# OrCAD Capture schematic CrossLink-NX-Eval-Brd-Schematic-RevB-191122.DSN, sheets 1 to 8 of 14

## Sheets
1 Title Page: title: Title page; rev: 1.0; note: 305-PD-19-0819
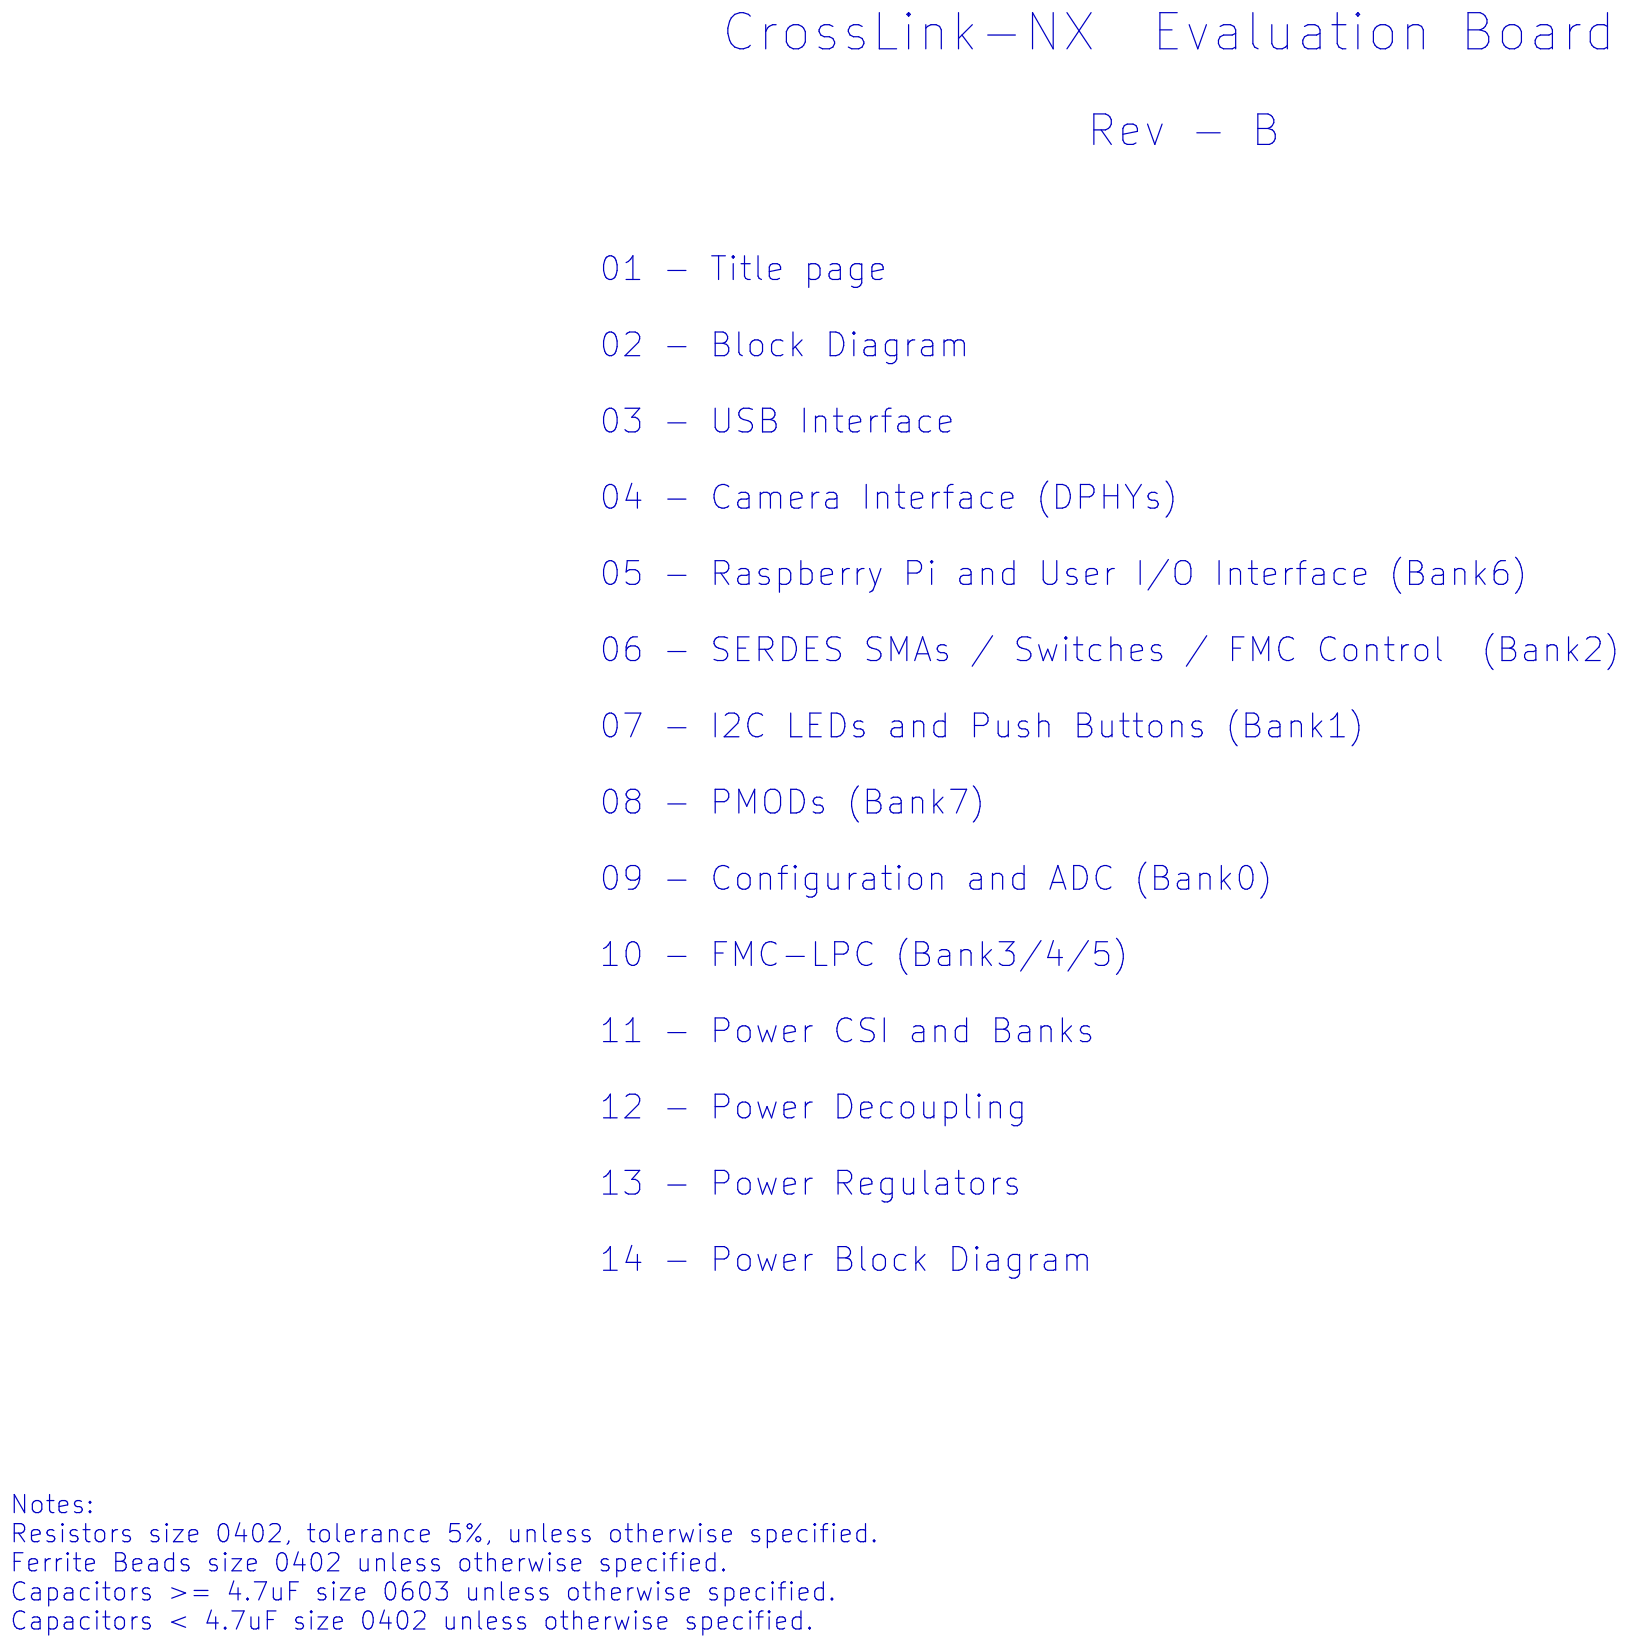
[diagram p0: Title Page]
2 Block Diagram: title: Block Diagram
3 USB Interface: size B; title: USB Interface
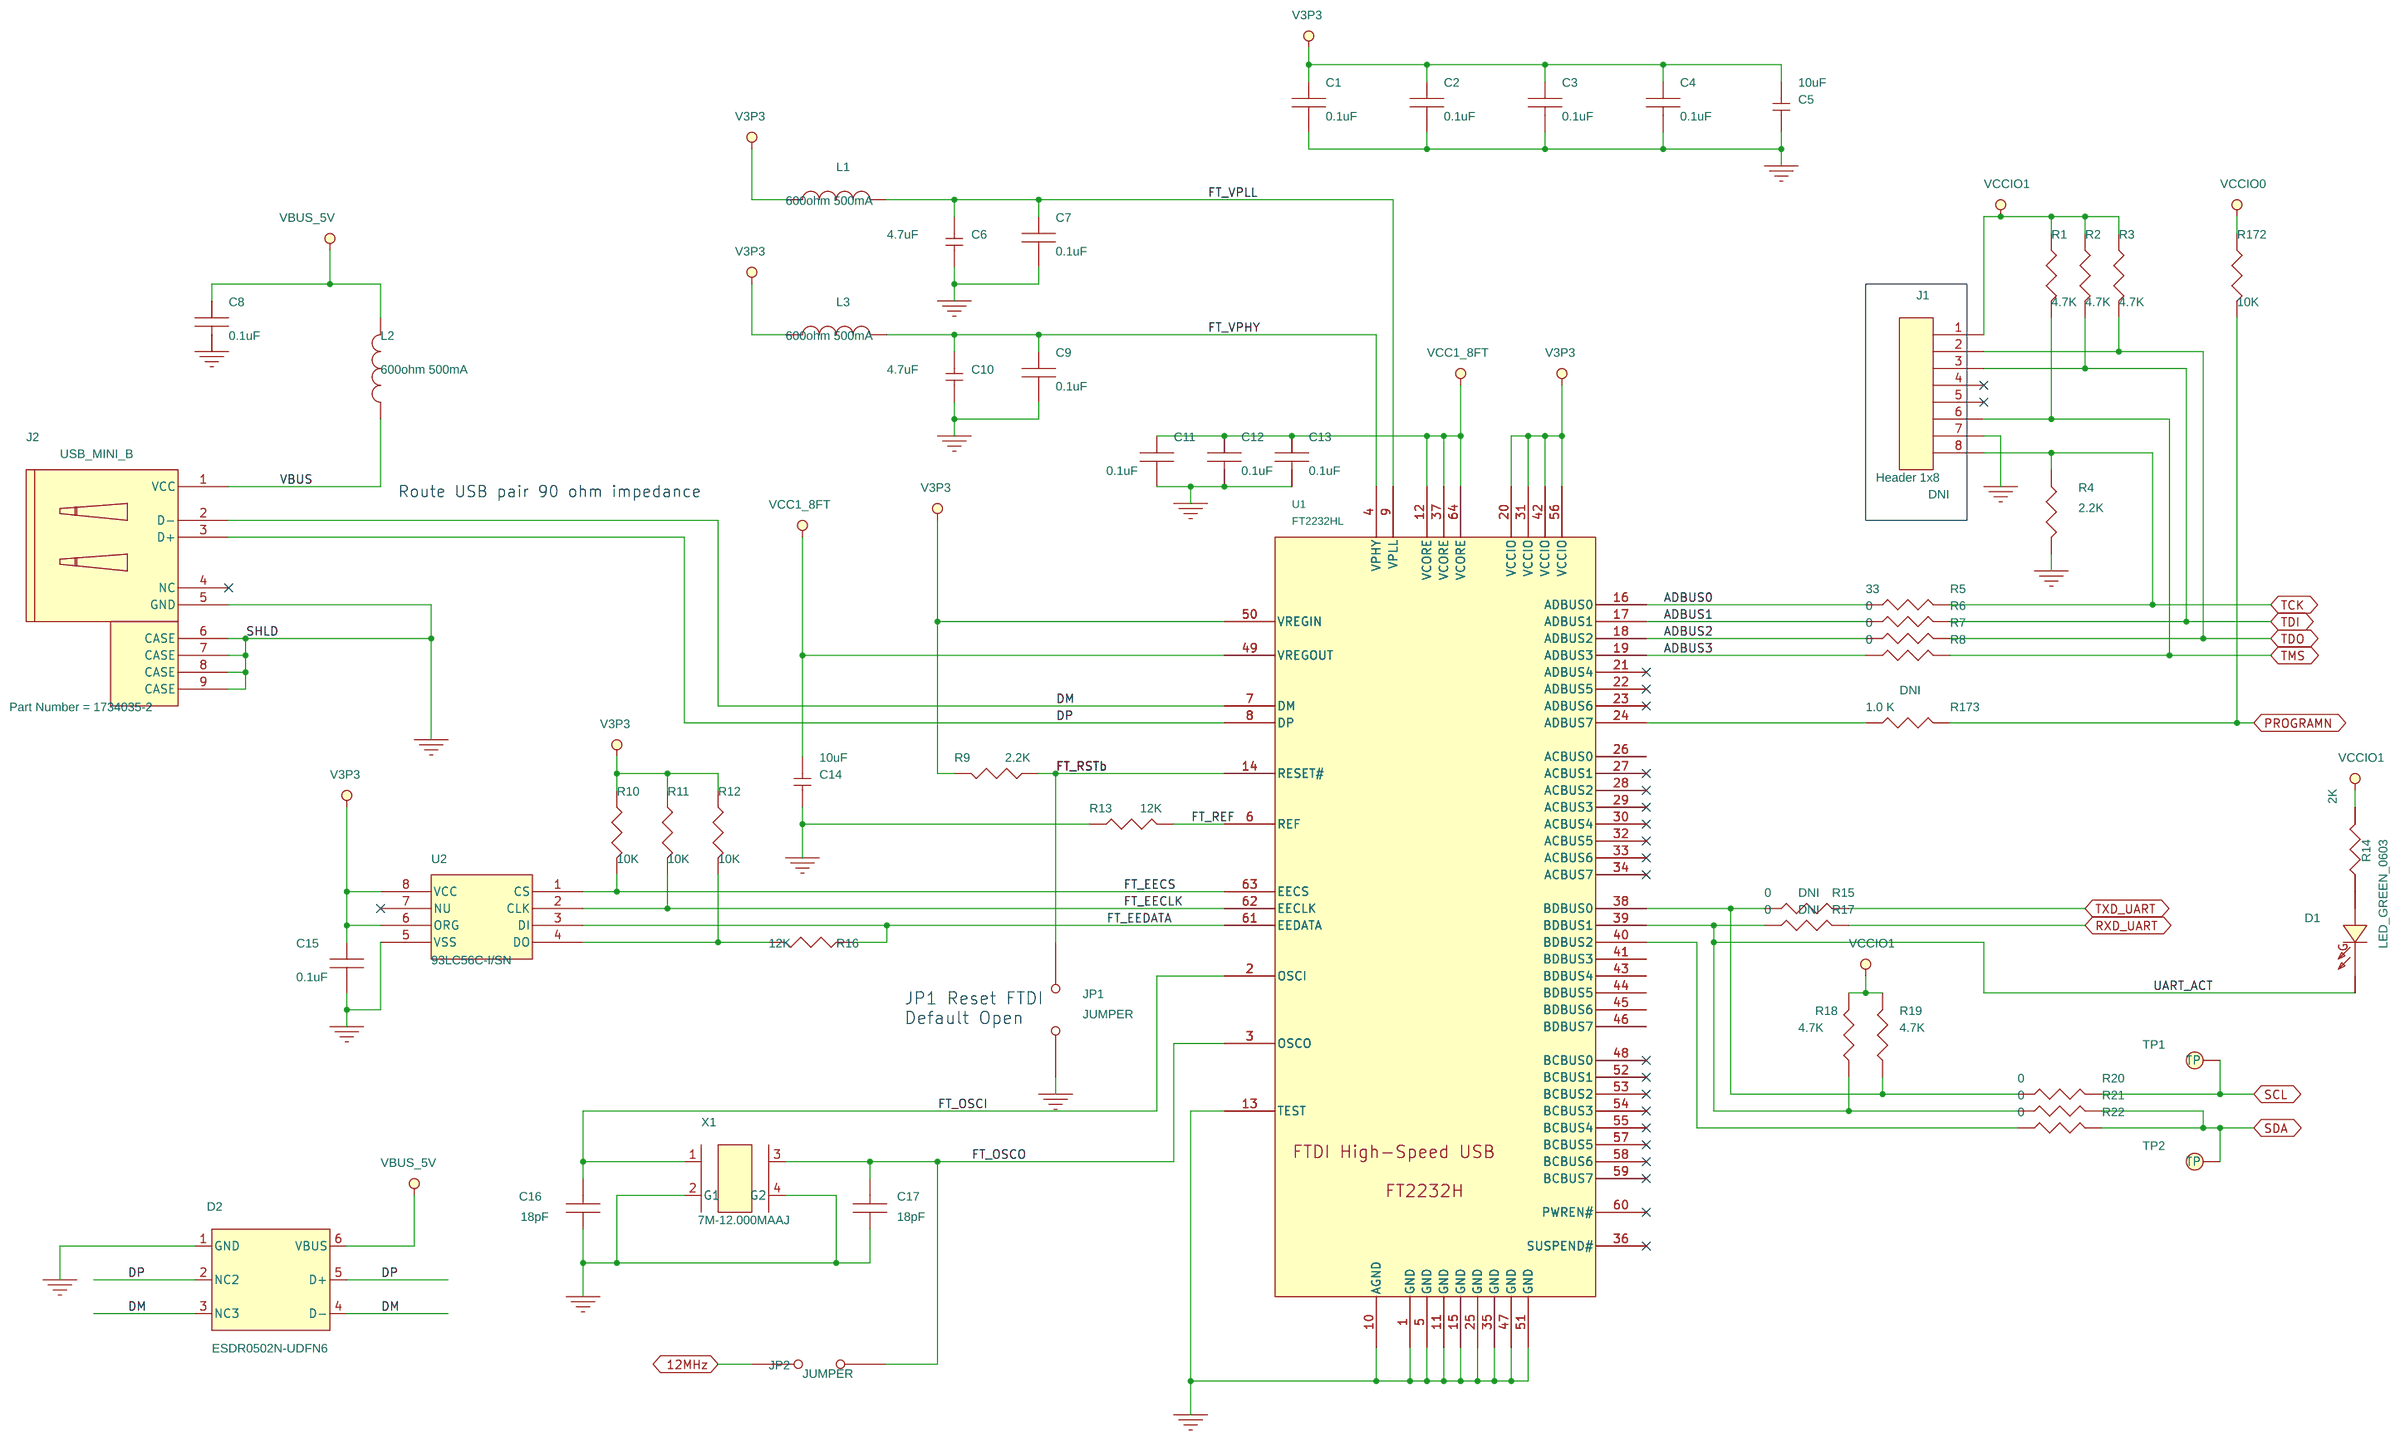
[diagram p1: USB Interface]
4 Camera Interface: size B; title: Camera Interface (DPHYs)
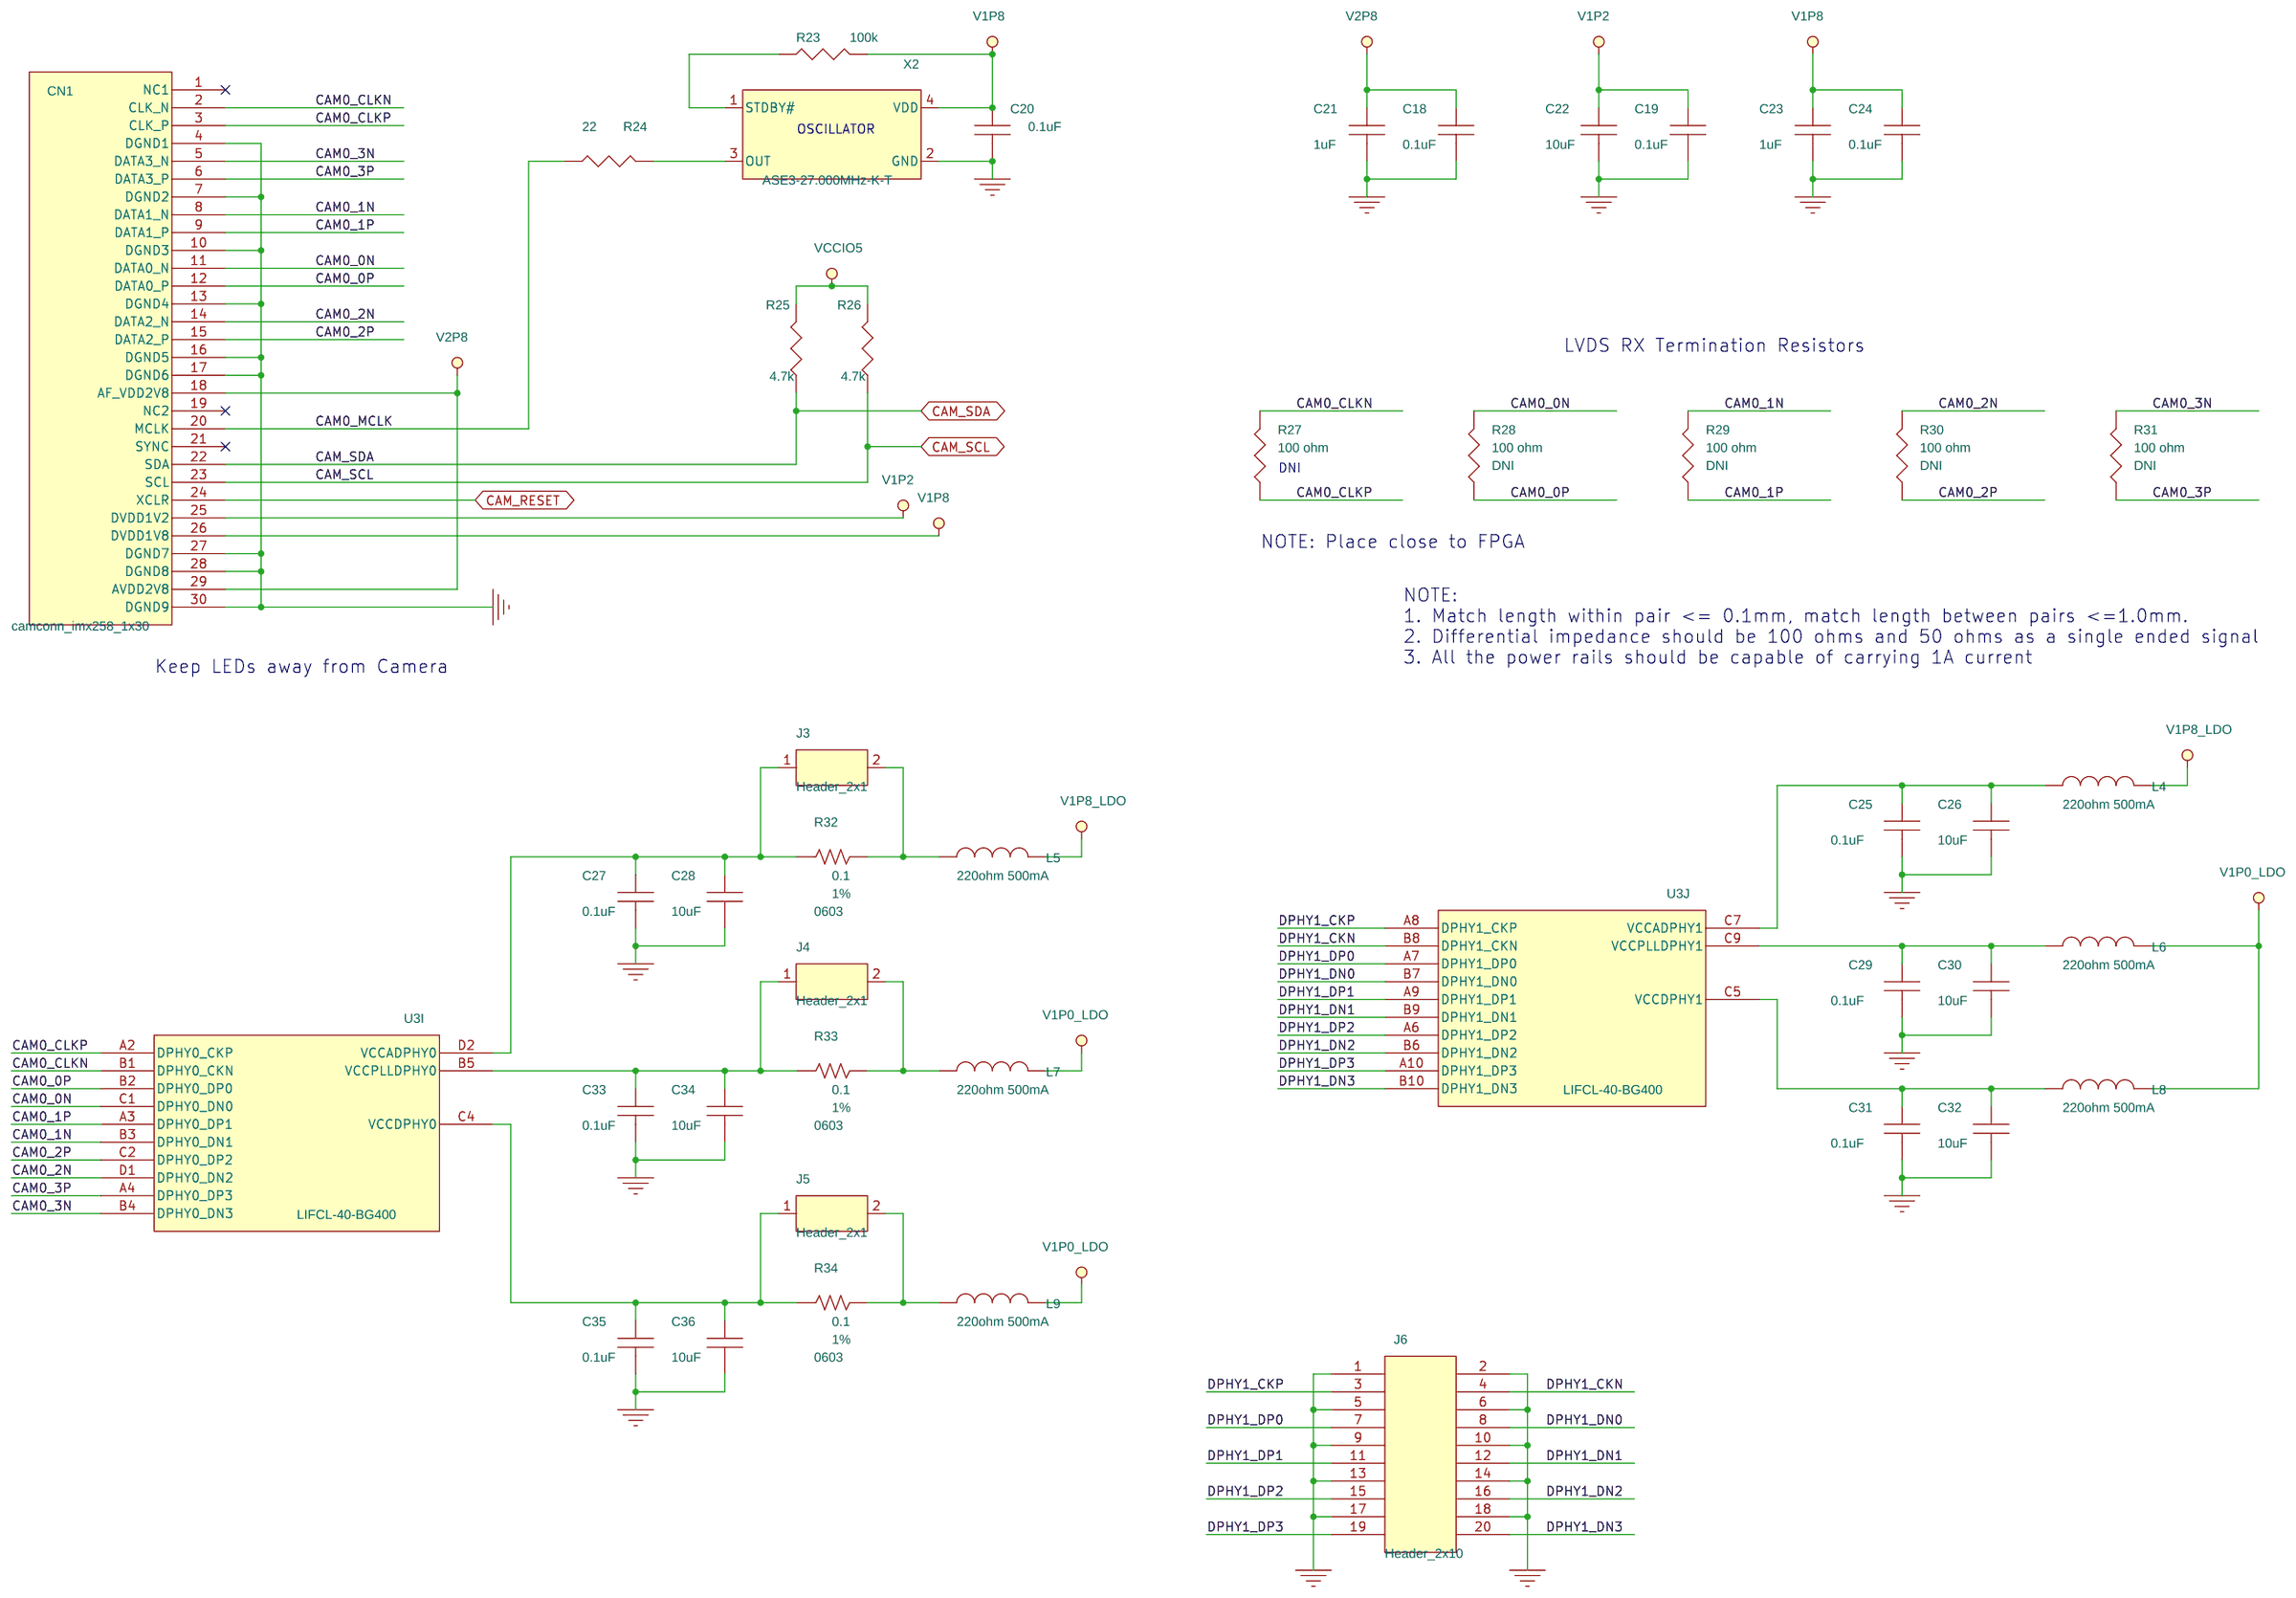
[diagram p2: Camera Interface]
5 Raspberry Pi: size B; title: Raspberry Pi and User I/O Interface
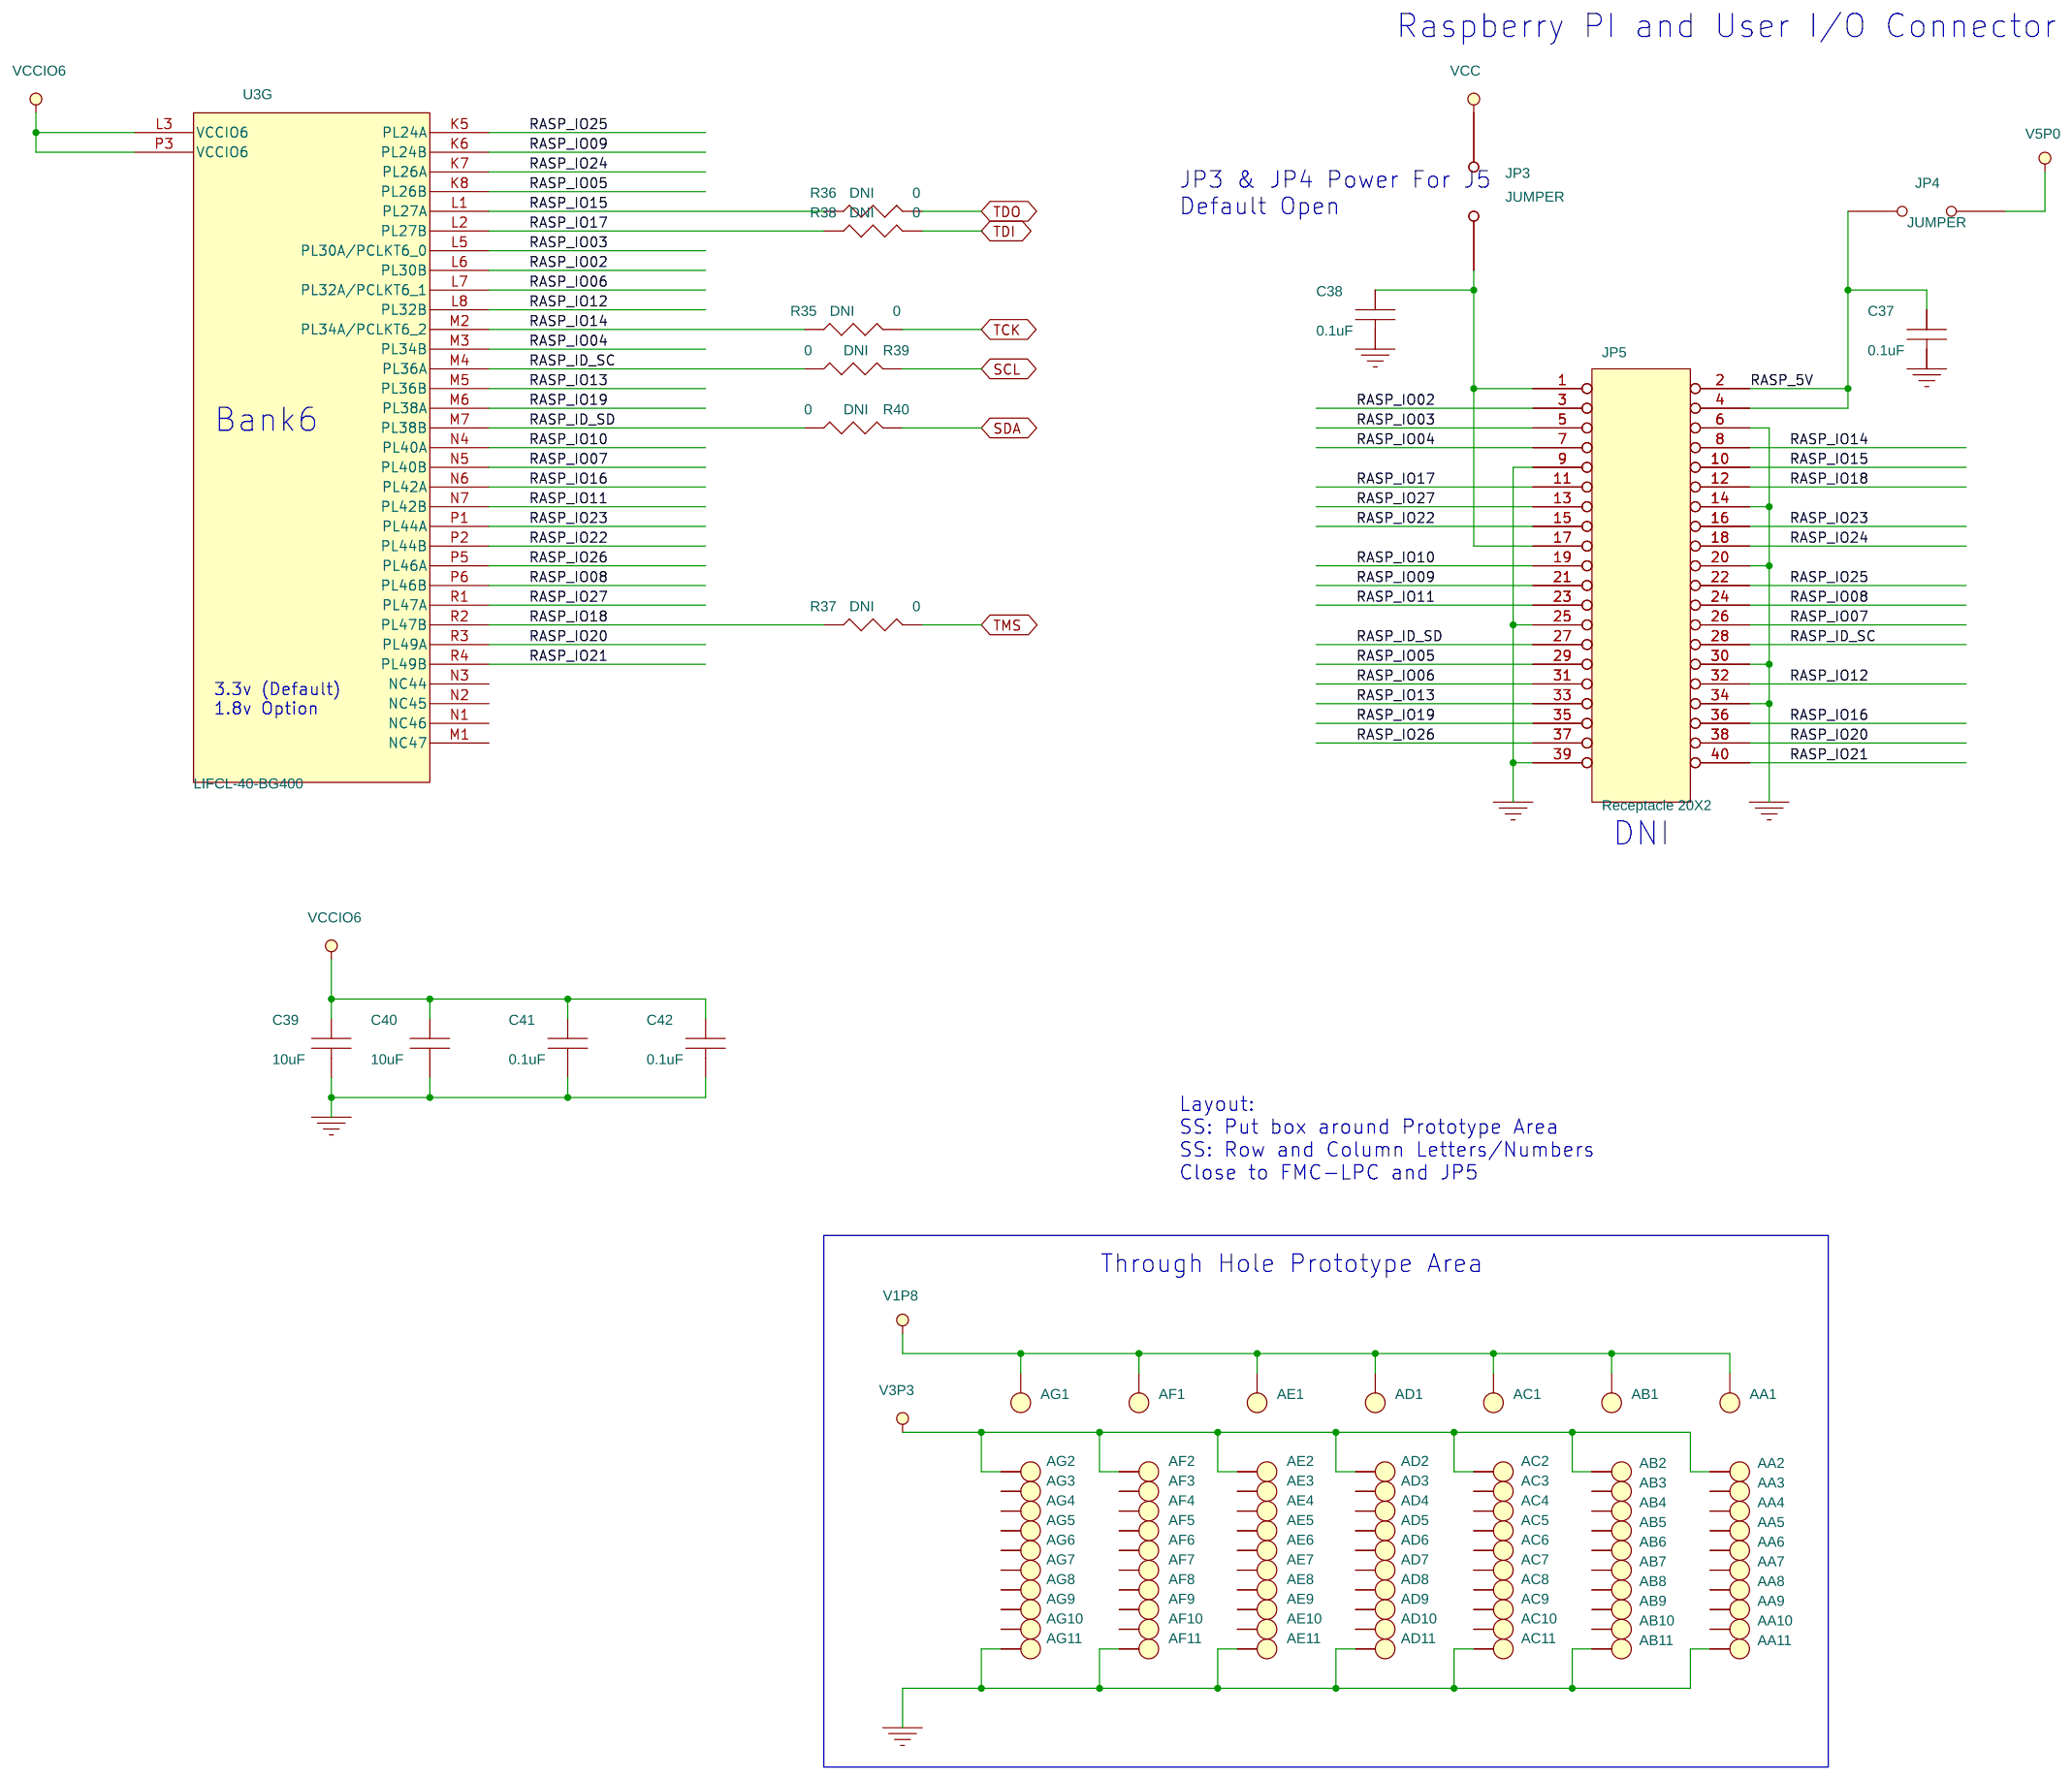
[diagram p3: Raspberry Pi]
6 Serdes SMAs And Switches: size B; title: Serdes SMAs/Switches/FMC Control
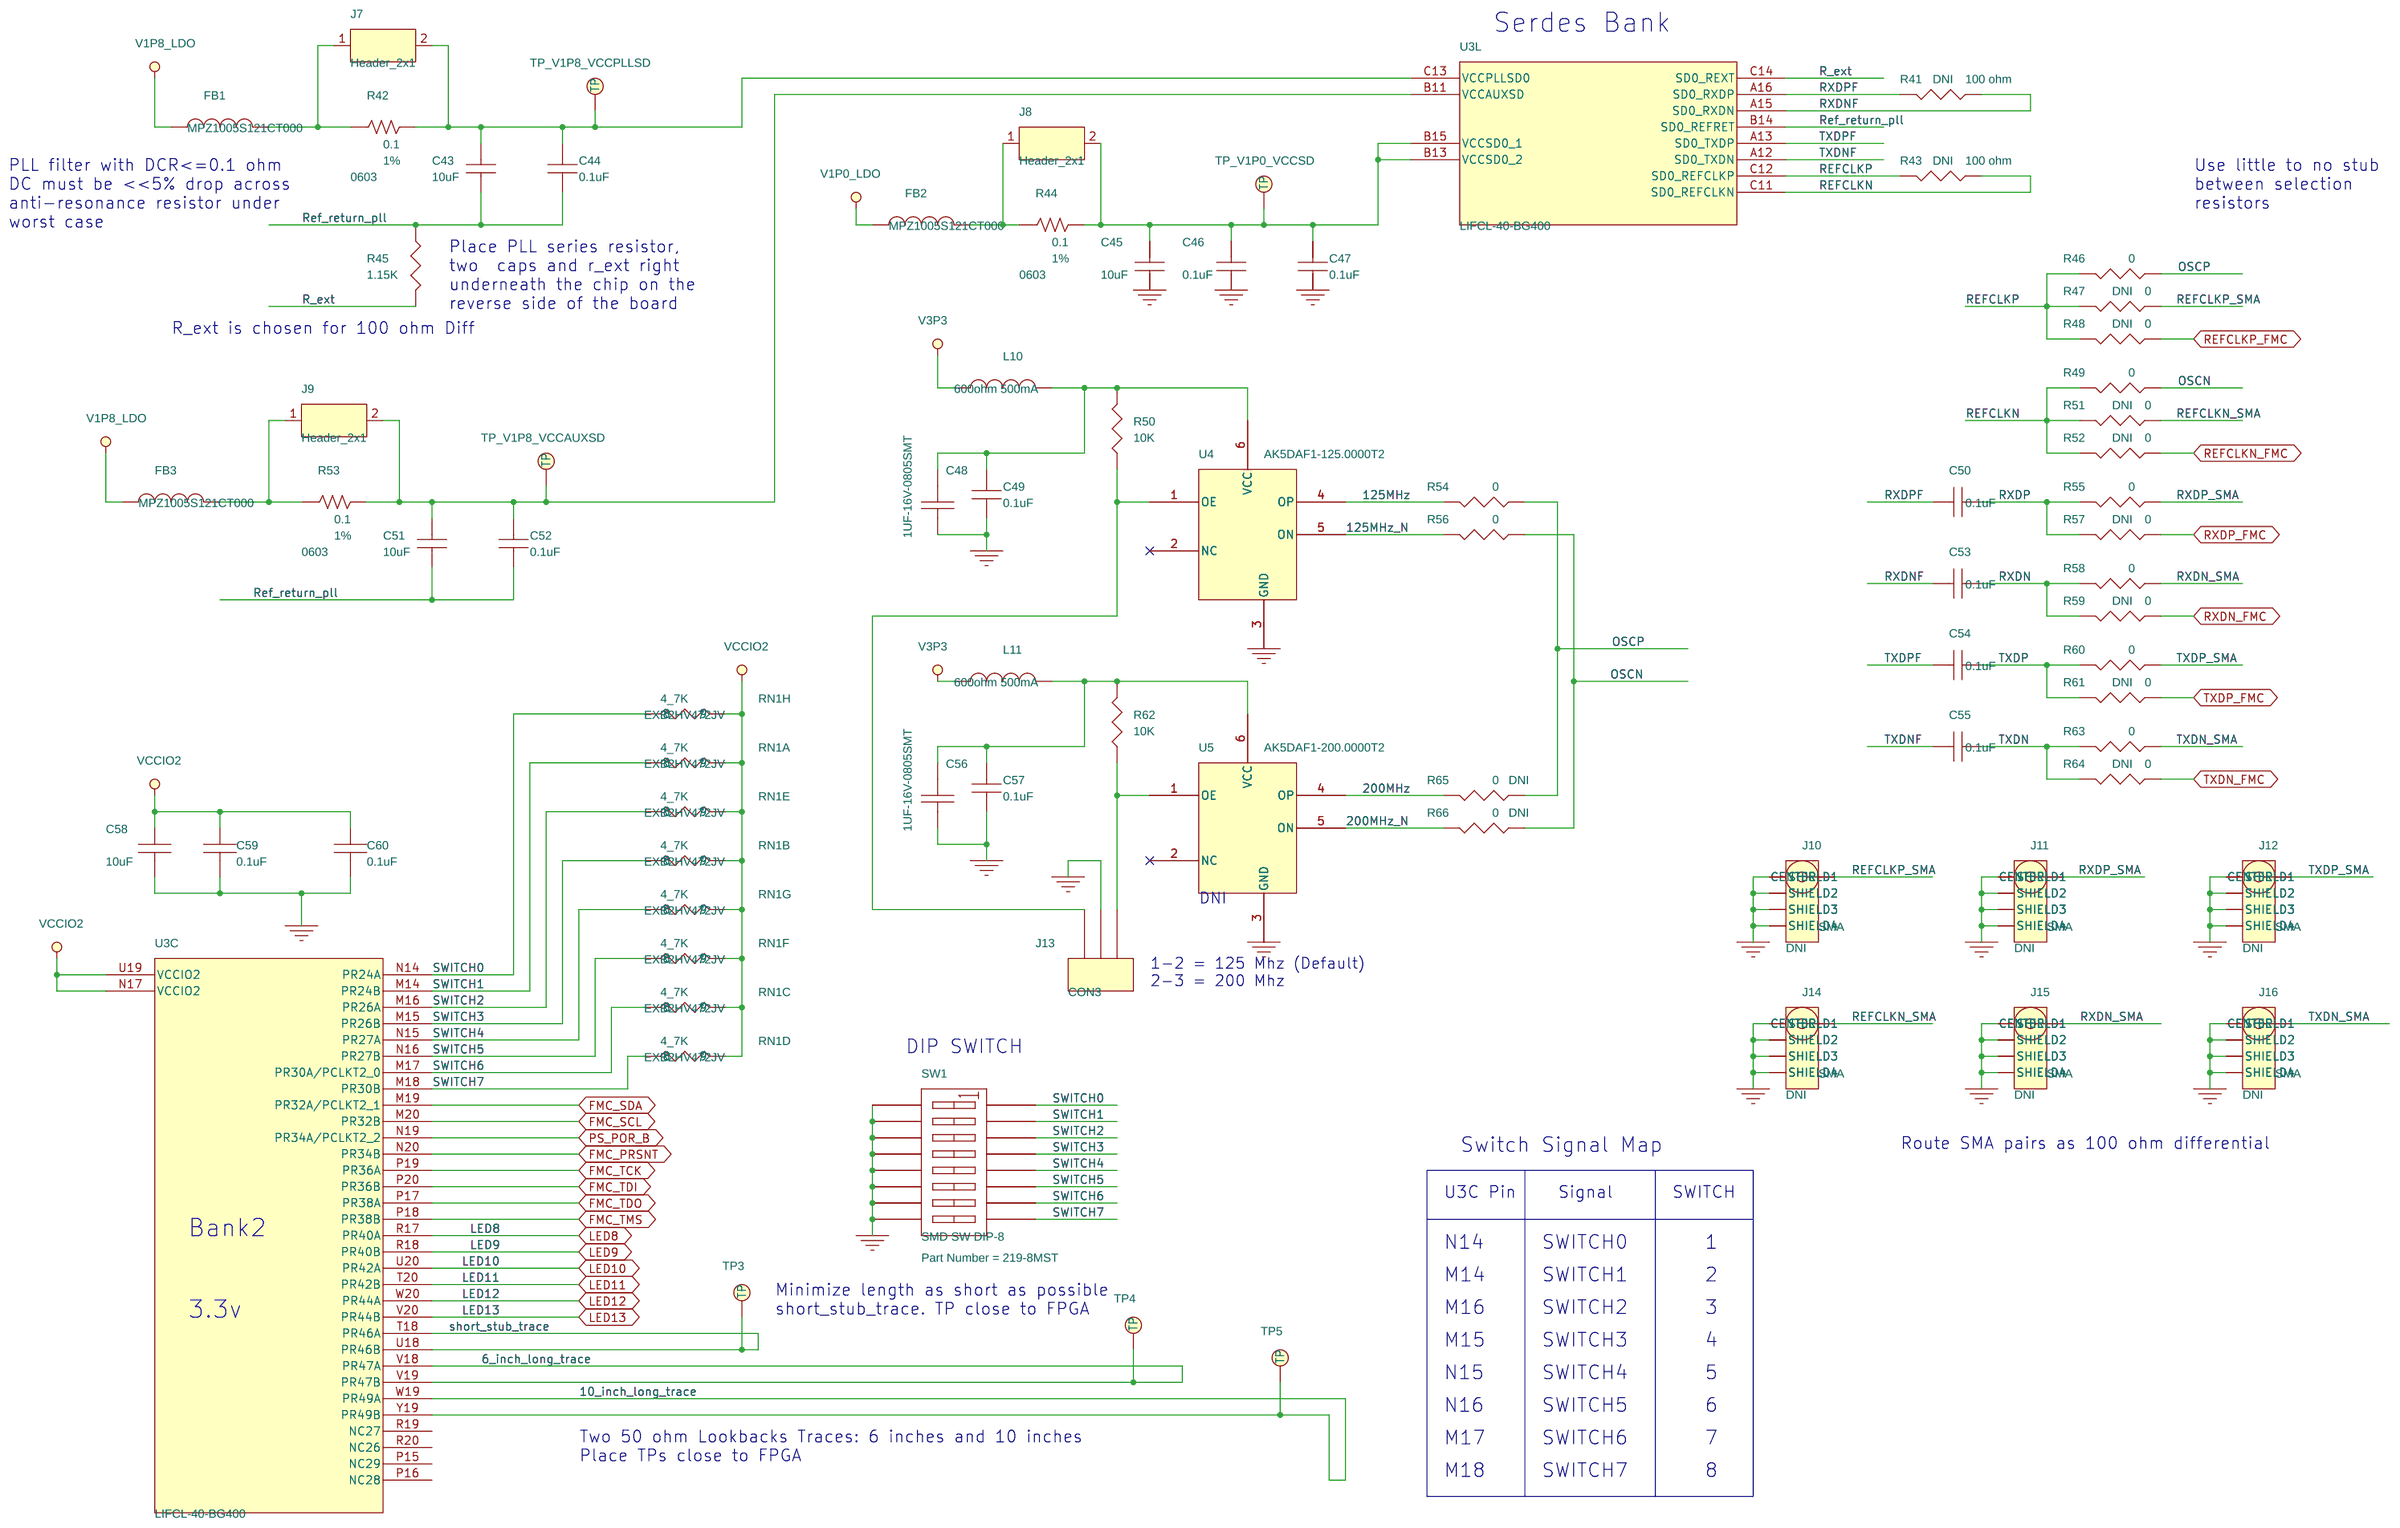
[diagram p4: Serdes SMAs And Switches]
7 I2C, LEDs And Push Button: size B; title: I2C LEDs And Push Buttons
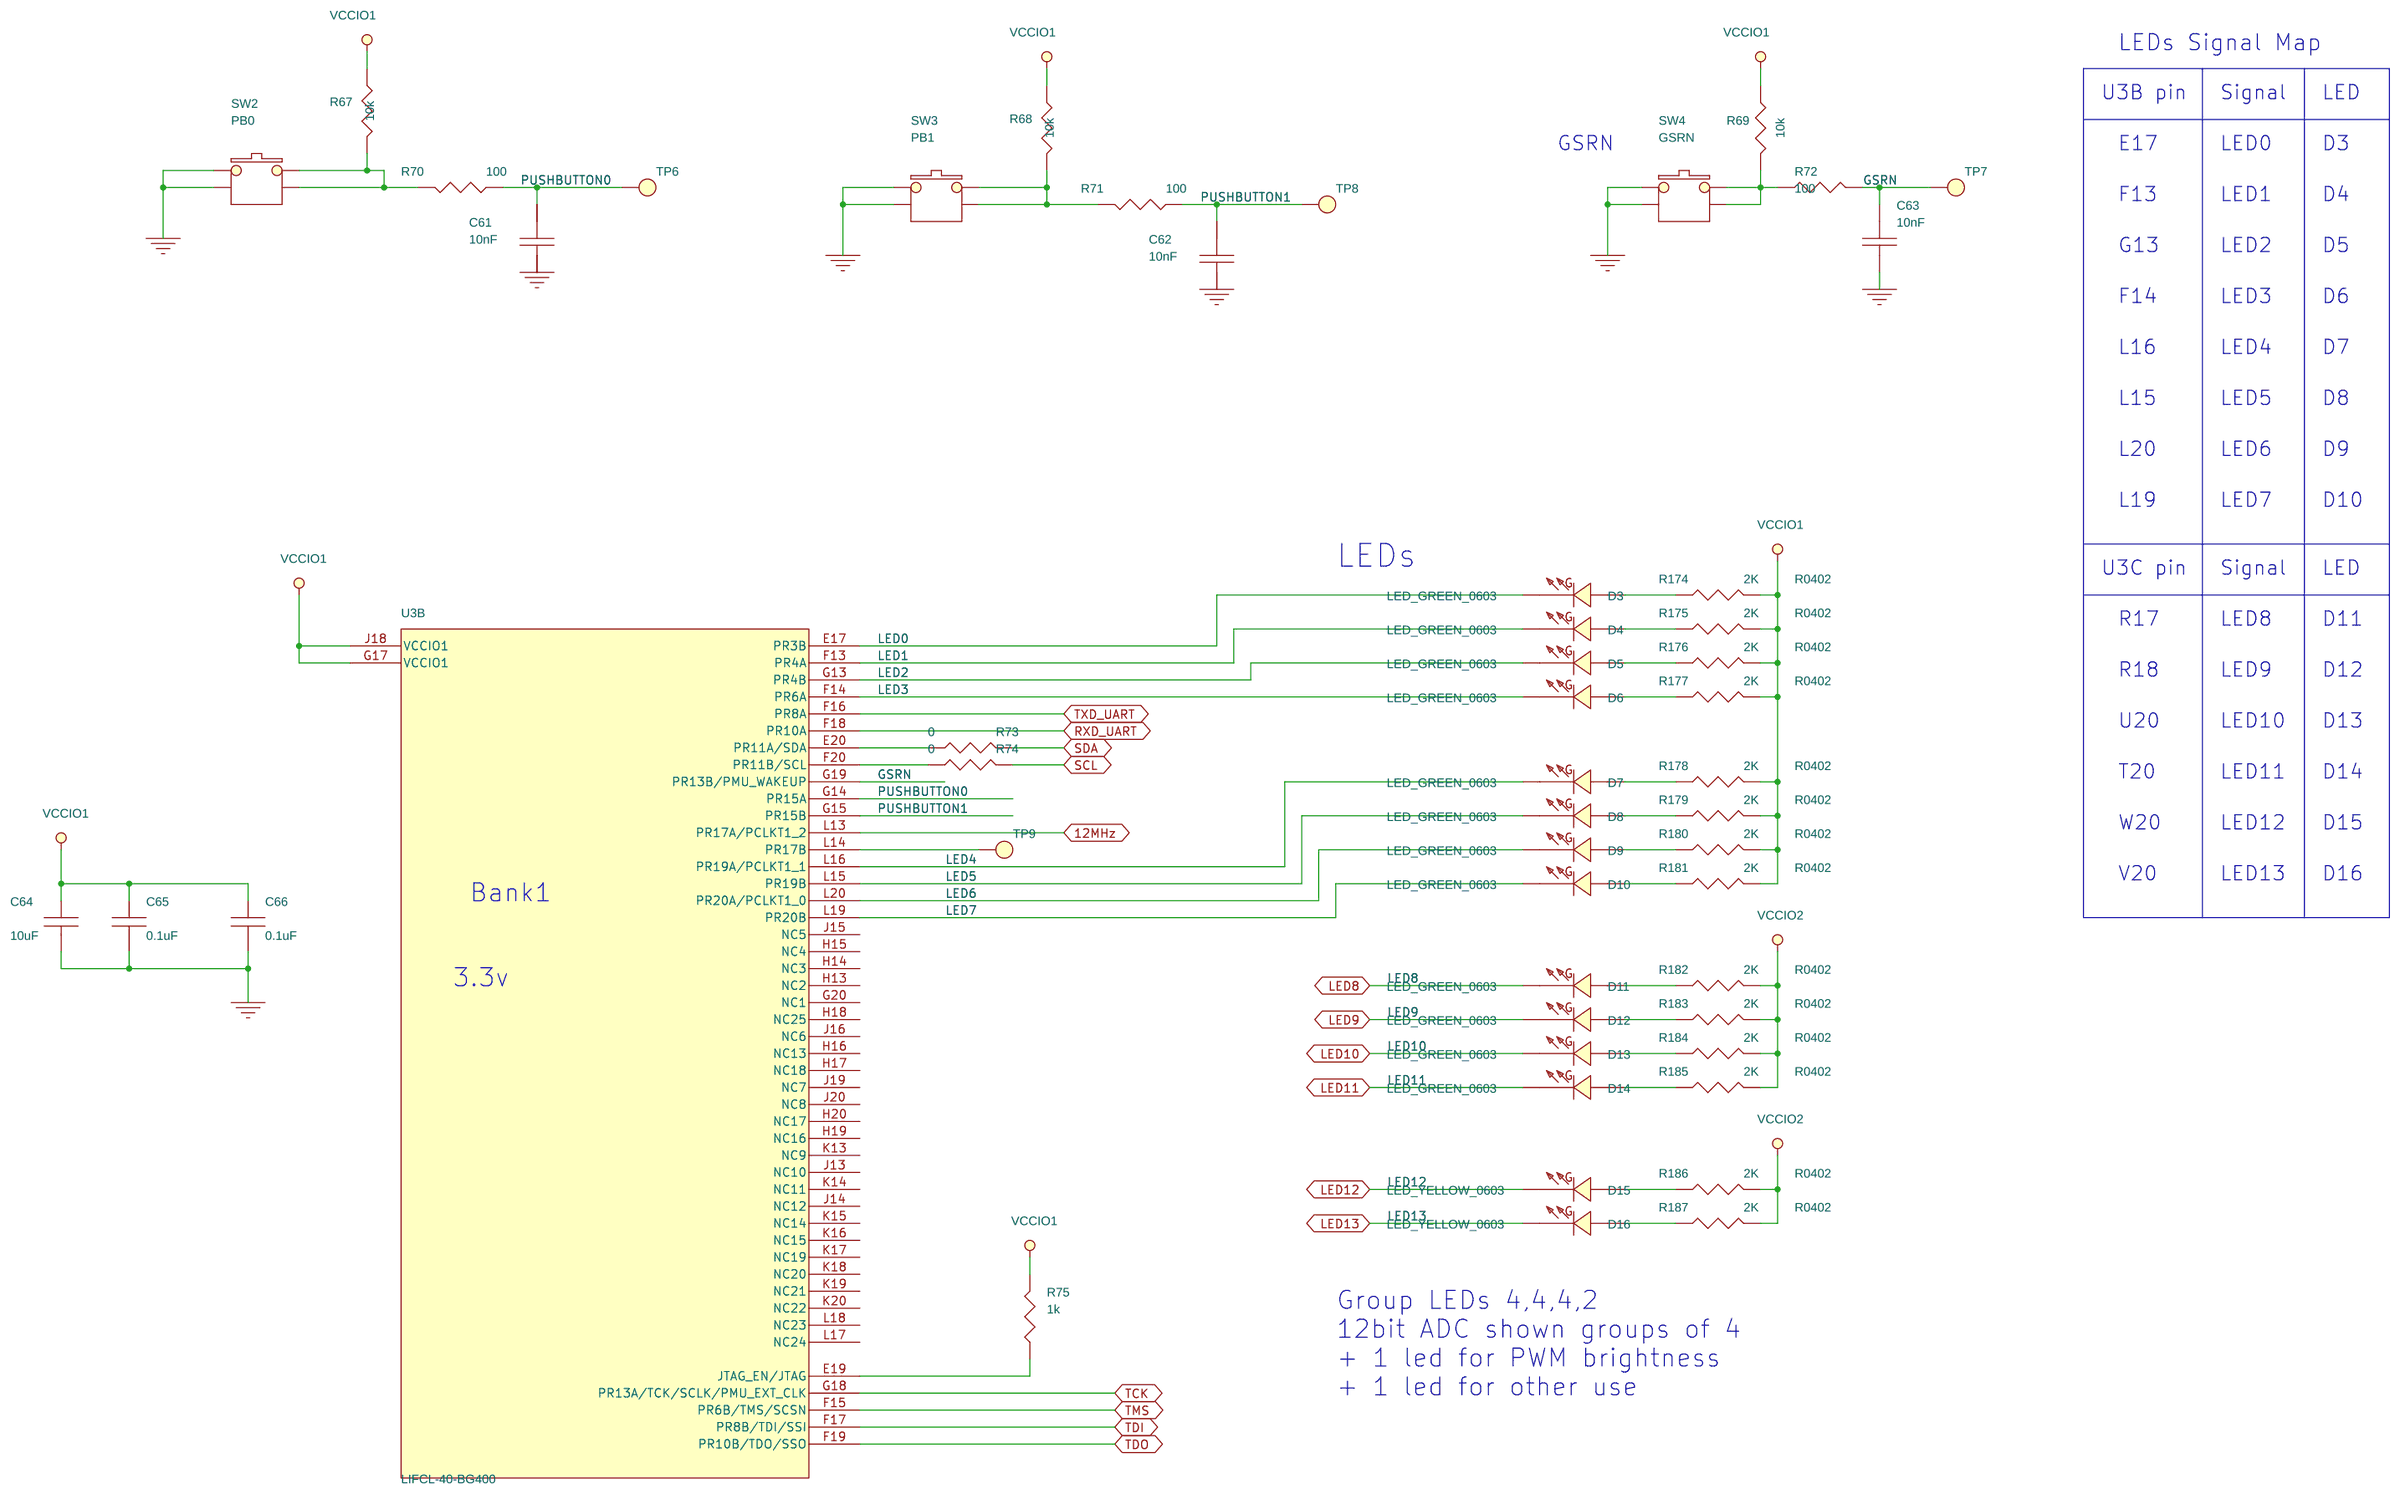
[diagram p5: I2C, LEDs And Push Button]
8 PMOD: size B; title: PMODs
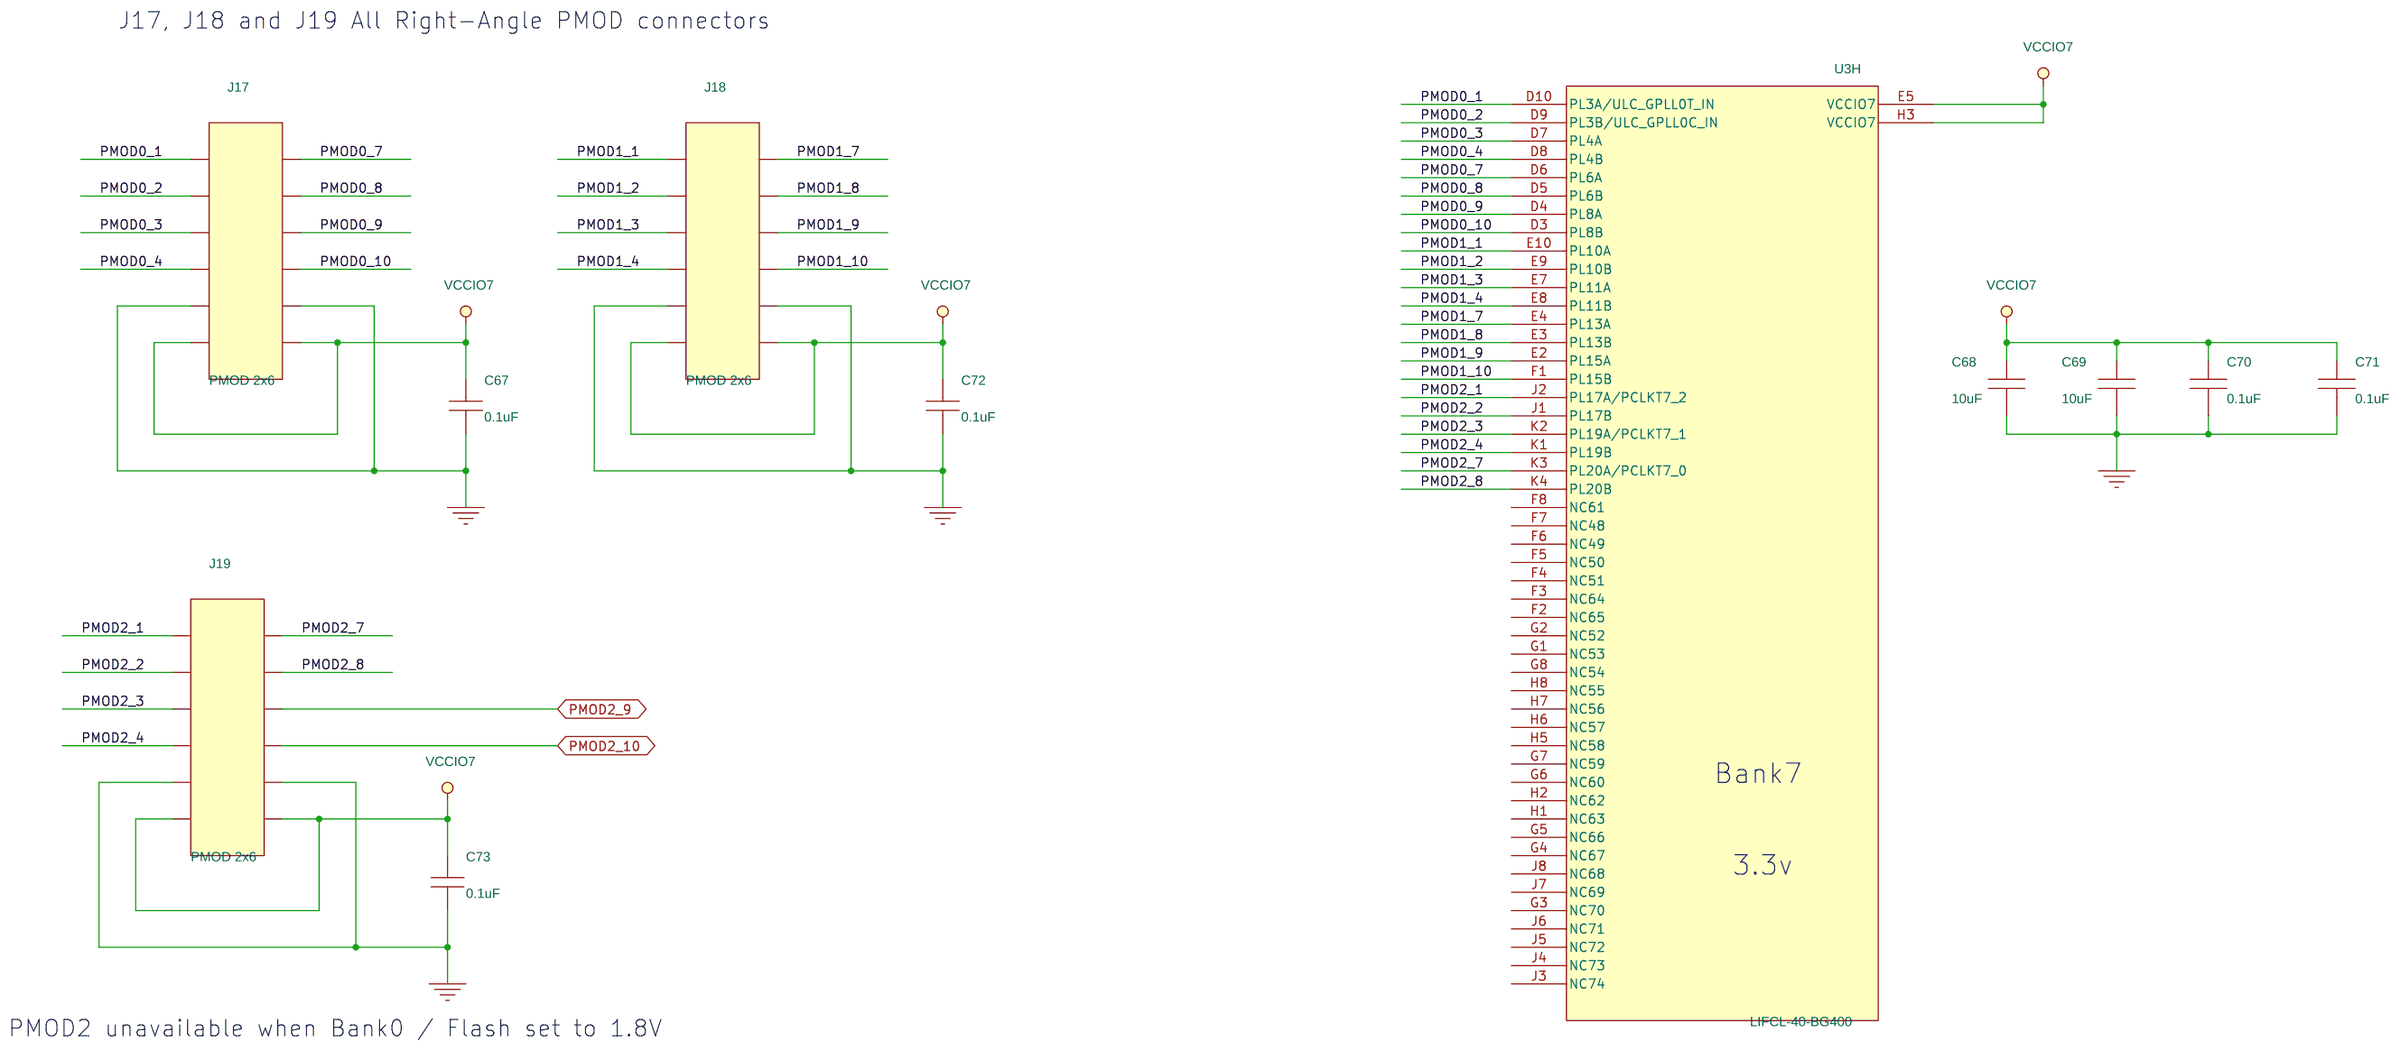
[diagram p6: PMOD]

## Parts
sheet Camera Interface
C18  0.1uF  [C0201]
C19  0.1uF  [C0201]
C20  0.1uF  [C0201]
C21  1uF  [C0603]
C22  10uF  [C0603]
C23  1uF  [C0603]
C24  0.1uF  [C0201]
C25  0.1uF  [C0201]
C26  10uF  [C0402]
C27  0.1uF  [C0201]
C28  10uF  [C0402]
C29  0.1uF  [C0201]
C30  10uF  [C0402]
C31  0.1uF  [C0201]
C32  10uF  [C0402]
C33  0.1uF  [C0201]
C34  10uF  [C0402]
C35  0.1uF  [C0201]
C36  10uF  [C0402]
CN1  camconn_imx258_1x30  [camconn]
J3  Header_2x1  [Header_2x1]
J4  Header_2x1  [Header_2x1]
J5  Header_2x1  [Header_2x1]
J6  Header_2x10  [Header_2x10]
L4  220ohm 500mA  [FB0402]
L5  220ohm 500mA  [FB0402]
L6  220ohm 500mA  [FB0402]
L7  220ohm 500mA  [FB0402]
L8  220ohm 500mA  [FB0402]
L9  220ohm 500mA  [FB0402]
R23  100k  [R0402]
R24  22  [R0402]
R25  4.7k  [R0402]
R26  4.7k  [R0402]
R27  100 ohm  [R0201]
R28  100 ohm  [R0201]
R29  100 ohm  [R0201]
R30  100 ohm  [R0201]
R31  100 ohm  [R0201]
R32  0.1  [0603]
R33  0.1  [0603]
R34  0.1  [0603]
X2  ASE3-27.000MHz-K-T  [27MHZ]
sheet I2C, LEDs And Push Button
C61  10nF  [RLP-130-A]
C62  10nF  [RLP-130-A]
C63  10nF  [RLP-130-A]
C64  10uF  [C0603]
C65  0.1uF  [C0201]
C66  0.1uF  [C0201]
D3  LED_GREEN_0603  [APT1608]
D4  LED_GREEN_0603  [APT1608]
D5  LED_GREEN_0603  [APT1608]
D6  LED_GREEN_0603  [APT1608]
D7  LED_GREEN_0603  [APT1608]
D8  LED_GREEN_0603  [APT1608]
D9  LED_GREEN_0603  [APT1608]
D10  LED_GREEN_0603  [APT1608]
D11  LED_GREEN_0603  [APT1608]
D12  LED_GREEN_0603  [APT1608]
D13  LED_GREEN_0603  [APT1608]
D14  LED_GREEN_0603  [APT1608]
D15  LED_YELLOW_0603  [APT1608]
D16  LED_YELLOW_0603  [APT1608]
R67  10k  [R0402]
R68  10k  [R0402]
R69  10k  [R0402]
R70  100  [R0402]
R71  100  [R0402]
R72  100  [R0402]
R73  0  [R0402]
R74  0  [R0402]
R75  1k  [R0402]
R174  2K  [R0402]
R175  2K  [R0402]
R176  2K  [R0402]
R177  2K  [R0402]
R178  2K  [R0402]
R179  2K  [R0402]
R180  2K  [R0402]
R181  2K  [R0402]
R182  2K  [R0402]
R183  2K  [R0402]
R184  2K  [R0402]
R185  2K  [R0402]
R186  2K  [R0402]
R187  2K  [R0402]
SW2  PB0  [4psmd_switch]
SW3  PB1  [4psmd_switch]
SW4  GSRN  [4psmd_switch]
TP6  TestPoint  [TP50]
TP7  TestPoint  [TP50]
TP8  TestPoint  [TP50]
TP9  TestPoint  [TP50]
sheet PMOD
C67  0.1uF  [C0201]
C68  10uF  [C0603]
C69  10uF  [C0603]
C70  0.1uF  [C0201]
C71  0.1uF  [C0201]
C72  0.1uF  [C0201]
C73  0.1uF  [C0201]
J17  PMOD 2x6  [PPPC062LJBN-RC]
J18  PMOD 2x6  [PPPC062LJBN-RC]
J19  PMOD 2x6  [PPPC062LJBN-RC]
sheet Raspberry Pi
AA1  T POINT R  [TP]
AA2  T POINT R  [TP]
AA3  T POINT R  [TP]
AA4  T POINT R  [TP]
AA5  T POINT R  [TP]
AA6  T POINT R  [TP]
AA7  T POINT R  [TP]
AA8  T POINT R  [TP]
AA9  T POINT R  [TP]
AA10  T POINT R  [TP]
AA11  T POINT R  [TP]
AB1  T POINT R  [TP]
AB2  T POINT R  [TP]
AB3  T POINT R  [TP]
AB4  T POINT R  [TP]
AB5  T POINT R  [TP]
AB6  T POINT R  [TP]
AB7  T POINT R  [TP]
AB8  T POINT R  [TP]
AB9  T POINT R  [TP]
AB10  T POINT R  [TP]
AB11  T POINT R  [TP]
AC1  T POINT R  [TP]
AC2  T POINT R  [TP]
AC3  T POINT R  [TP]
AC4  T POINT R  [TP]
AC5  T POINT R  [TP]
AC6  T POINT R  [TP]
AC7  T POINT R  [TP]
AC8  T POINT R  [TP]
AC9  T POINT R  [TP]
AC10  T POINT R  [TP]
AC11  T POINT R  [TP]
AD1  T POINT R  [TP]
AD2  T POINT R  [TP]
AD3  T POINT R  [TP]
AD4  T POINT R  [TP]
AD5  T POINT R  [TP]
AD6  T POINT R  [TP]
AD7  T POINT R  [TP]
AD8  T POINT R  [TP]
AD9  T POINT R  [TP]
AD10  T POINT R  [TP]
AD11  T POINT R  [TP]
AE1  T POINT R  [TP]
AE2  T POINT R  [TP]
AE3  T POINT R  [TP]
AE4  T POINT R  [TP]
AE5  T POINT R  [TP]
AE6  T POINT R  [TP]
AE7  T POINT R  [TP]
AE8  T POINT R  [TP]
AE9  T POINT R  [TP]
AE10  T POINT R  [TP]
AE11  T POINT R  [TP]
AF1  T POINT R  [TP]
AF2  T POINT R  [TP]
AF3  T POINT R  [TP]
AF4  T POINT R  [TP]
AF5  T POINT R  [TP]
AF6  T POINT R  [TP]
AF7  T POINT R  [TP]
AF8  T POINT R  [TP]
AF9  T POINT R  [TP]
AF10  T POINT R  [TP]
AF11  T POINT R  [TP]
AG1  T POINT R  [TP]
AG2  T POINT R  [TP]
AG3  T POINT R  [TP]
AG4  T POINT R  [TP]
AG5  T POINT R  [TP]
AG6  T POINT R  [TP]
AG7  T POINT R  [TP]
AG8  T POINT R  [TP]
AG9  T POINT R  [TP]
AG10  T POINT R  [TP]
AG11  T POINT R  [TP]
C37  0.1uF  [C0201]
C38  0.1uF  [C0201]
C39  10uF  [C0603]
C40  10uF  [C0603]
C41  0.1uF  [C0201]
C42  0.1uF  [C0201]
JP3  JUMPER  [Header_1x2]
JP4  JUMPER  [Header_1x2]
JP5  Receptacle 20X2  [HDR254-2X20_socket]
R35  0  [R0603]
R36  0  [R0603]
R37  0  [R0603]
R38  0  [R0603]
R39  0  [R0603]
R40  0  [R0603]
U3  LIFCL-40-BG400  [LIFCL-40-BG400]  (sections A,B,C,D,E,F,G,H,I,J,K,L,M,N,O)
sheet Serdes SMAs And Switches
C43  10uF  [C0402]
C44  0.1uF  [C0201]
C45  10uF  [C0402]
C46  0.1uF  [C0201]
C47  0.1uF  [C0201]
C48  1UF-16V-0805SMT  [RLP-133]
C49  0.1uF  [C0201]
C50  0.1uF  [C0201]
C51  10uF  [C0402]
C52  0.1uF  [C0201]
C53  0.1uF  [C0201]
C54  0.1uF  [C0201]
C55  0.1uF  [C0201]
C56  1UF-16V-0805SMT  [RLP-133]
C57  0.1uF  [C0201]
C58  10uF  [C0603]
C59  0.1uF  [C0201]
C60  0.1uF  [C0201]
FB1  MPZ1005S121CT000  [FB0402]
FB2  MPZ1005S121CT000  [FB0402]
FB3  MPZ1005S121CT000  [FB0402]
J7  Header_2x1  [Header_2x1]
J8  Header_2x1  [Header_2x1]
J9  Header_2x1  [Header_2x1]
J10  SMA  [901-10309]
J11  SMA  [901-10309]
J12  SMA  [901-10309]
J13  CON3  [CON3]
J14  SMA  [901-10309]
J15  SMA  [901-10309]
J16  SMA  [901-10309]
L10  600ohm 500mA  [fb0603]
L11  600ohm 500mA  [fb0603]
R41  100 ohm  [R0201]
R42  0.1  [0603]
R43  100 ohm  [R0201]
R44  0.1  [0603]
R45  1.15K  [R0402]
R46  0  [R0402]
R47  0  [R0402]
R48  0  [R0402]
R49  0  [R0402]
R50  10K  [RLP-100]
R51  0  [R0402]
R52  0  [R0402]
R53  0.1  [0603]
R54  0  [R0402]
R55  0  [R0402]
R56  0  [R0402]
R57  0  [R0402]
R58  0  [R0402]
R59  0  [R0402]
R60  0  [R0402]
R61  0  [R0402]
R62  10K  [RLP-100]
R63  0  [R0402]
R64  0  [R0402]
R65  0  [R0402]
R66  0  [R0402]
RN1  EXB2HV472JV  [EXB-2HV]  (sections A,B,C,D,E,F,G,H)
SW1  SMD SW DIP-8  [219-8MST]
TP3  TP_S_40_63  [TP]
TP4  TP_S_40_63  [TP]
TP5  TP_S_40_63  [TP]
TP_V1P0_VCCSD  TP_S_40_63  [tp_s_40_63]
TP_V1P8_VCCAUXSD  TP_S_40_63  [tp_s_40_63]
TP_V1P8_VCCPLLSD  TP_S_40_63  [tp_s_40_63]
U4  AK5DAF1-125.0000T2  [XTAL_AK5DAF1]
U5  AK5DAF1-200.0000T2  [XTAL_AK5DAF1]
sheet USB Interface
C1  0.1uF  [C0201]
C2  0.1uF  [C0201]
C3  0.1uF  [C0201]
C4  0.1uF  [C0201]
C5  10uF  [C0603]
C6  4.7uF  [C0603]
C7  0.1uF  [C0201]
C8  0.1uF  [C0201]
C9  0.1uF  [C0201]
C10  4.7uF  [C0603]
C11  0.1uF  [C0201]
C12  0.1uF  [C0201]
C13  0.1uF  [C0201]
C14  10uF  [C0603]
C15  0.1uF  [C0201]
C16  18pF  [C0402]
C17  18pF  [C0402]
D1  LED_GREEN_0603  [APT1608]
D2  ESDR0502N-UDFN6  [UDFN6_040]
J1  Header 1x8  [hdr_amp_87220_8_1x8_100]
J2  USB_MINI_B  [USB_MINI_B-1734035-2]
JP1  JUMPER  [Header_1x2]
JP2  JUMPER  [Header_1x2]
L1  600ohm 500mA  [fb0603]
L2  600ohm 500mA  [fb0603]
L3  600ohm 500mA  [fb0603]
R1  4.7K  [R0603]
R2  4.7K  [R0603]
R3  4.7K  [R0603]
R4  2.2K  [R0603]
R5  33  [R0402]
R6  0  [R0603]
R7  0  [R0603]
R8  0  [R0603]
R9  2.2K  [R0603]
R10  10K  [R0603]
R11  10K  [R0603]
R12  10K  [R0603]
R13  12K  [R0603]
R14  2K  [RLP-101]
R15  0  [R0603]
R16  12K  [R0603]
R17  0  [R0603]
R18  4.7K  [RLP-101]
R19  4.7K  [RLP-101]
R20  0  [R0603]
R21  0  [R0603]
R22  0  [R0603]
R172  10K  [R0603]
R173  1.0 K  [R0603]
TP1  TP_S_40_63  [TP]
TP2  TP_S_40_63  [TP]
U1  FT2232HL  [tqfp64_0p5_12p2x12p2_h1p6]
U2  93LC56C-I/SN  [so8_50_244]
X1  7M-12.000MAAJ  [xtal_4p_7m]

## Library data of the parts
C1-C4 C7-C9 C11-C13 C15 C18-C20 C24 C25 C27 C29 C31 C33 C35 C37 C38 C41 C42 C59 C60 C65 C66 C70 C71 = 0u1_0402: CAP CER 0.1UF 25V 10% X5R 0201; Manufacturer: Murata; Manufacturer Part Number: GRM033R61E104KE14J
C21-C23 C39 C58 C64 C68 C69 = 10uF_0603
C26 C28 C30 C32 C34 C36 = 10uF_0603: CAP CER 10UF 10V X5R 0402; Manufacturer: Samsung; Manufacturer Part Number: CL05A106MP8NUB8
CN1 = camconn_imx258_0
J3-J5 J7-J9 = Header_2x1
J6 = Header_2x10
L4-L9 = FB0603: FERRITE BEAD 600 OHM 0402 1LN; Manufacturer Part Number: BLM15AX601SN1D
R23 R75 = RES_100K_1W16_0402_5P: RES 100K OHM 1/10W 1% 0402 SMD; MFG: Panasonic; MFG P/N: ERJ-2RKF1003X; Manufacturer: Panasonic; Manufacturer Part Number: ERJ-2RKF1003X; PART_NUMBER: ERJ-2RKF1003X
R24 = 0R_0603: RES SMD 22 OHM 1% 1/10W 0402; MFG: Panasonic; MFG P/N: ERJ-2RKF22R0X; Manufacturer: Panasonic; Manufacturer Part Number: ERJ-2RKF22R0X
R25 R26 = 5k1_0402: RES SMD 2.2K OHM 1% 1/10W 0402; Manufacturer: Panasonic; Manufacturer Part Number: ERJ-2RKF2201X
R27-R31 R41 R43 = RES_100K_1W16_0402_5P: RES SMD 100 OHM 1% 1/20W 0201; Assy: DNI; MFG: Yageo; MFG P/N: RC0201FR-07100RL; Manufacturer: Yageo; Manufacturer Part Number: RC0201FR-07100RL
R32-R34 R42 R44 R53 = R_v3: COMPFIXED: NO; COMPGROUP: 0; COMPHEIGHT: 0.000; COMPKEY: NO; COMPLOC: [970.000,1160.000]; COMPLOCKED: NO; COMPROT: 180; COMPSIDE: TOP; DECOUPLER: NO; FPLIST: AX/RC05,SM/R_0603; MEMORY: NO; Tollerance: 1%
X2 = OSC_25MHz_10PPM: Standard Clock Oscillators 27.000M 1.8V 30ppm; Manufacturer: ABRACON
C61-C63 = CAP_1
D1 D3-D16 = LED-SMT1206_GREEN_1
R67-R69 = RES_0: RES SMD 10K OHM 1% 1/16W 0402; MFG: Yageo; MFG P/N: RC0402FR-0710KL; Manufacturer: Yageo; Manufacturer Part Number: RC0402FR-0710KL
R70-R72 = 0R_0603: RES SMD 100 OHM 1% 1/16W 0402; MFG: Yageo; Manufacturer Part Number: RC0402FR-07100RL
R73 R74 = R: RES SMD 33 OHM 1% 1/10W 0402; Manufacturer: Panasonic; Manufacturer Part Number: ERJ-2RKF33R0X
R174-R187 = RES_0: RES SMD 2K OHM 5% 1/10W 0402; MFG: Panasonic; MFG P/N: ERJ-2GEJ202X; Manufacturer: Panasonic; Manufacturer Part Number: ERJ-2GEJ202X
SW2-SW4 = SW_PUSHBUTTON-SPST_SM: SWITCH TACTILE SPST-NO 0.05A 12V; MFG: Wurth; MFG P/N: 434153017835; Man. Part #: 434153017835; Manufacturer: Wurth; Manufacturer Part Number: 434153017835
TP6-TP9 = T_POINT_R
C67 C72 C73 = C0402C104K4RACTU: CAP CER 0.1UF 25V 10% X5R 0201; Manufacturer: Murata; Manufacturer Part Number: GRM033R61E104KE14J
J17-J19 = SKT2x6_PPPC062LFBN-RC: CONN HDR 12POS 0.1 GOLD PCB R/A; Manufacturer: Sullins
AA1 AA2 = T_POINT_R_0: Assy: DNI; COMPFIXED: NO; COMPGROUP: 0; COMPHEIGHT: 0.000; COMPKEY: NO; COMPLOC: [100.000,3800.000]; COMPLOCKED: NO; COMPROT: 0; COMPSIDE: TOP; DECOUPLER: NO; MEMORY: NO
AA3 = T_POINT_R_0: Assy: DNI; COMPFIXED: NO; COMPGROUP: 0; COMPHEIGHT: 0.000; COMPKEY: NO; COMPLOC: [100.000,3700.000]; COMPLOCKED: NO; COMPROT: 0; COMPSIDE: TOP; DECOUPLER: NO; MEMORY: NO
AA4 = T_POINT_R_0: Assy: DNI; COMPFIXED: NO; COMPGROUP: 0; COMPHEIGHT: 0.000; COMPKEY: NO; COMPLOC: [100.000,3600.000]; COMPLOCKED: NO; COMPROT: 0; COMPSIDE: TOP; DECOUPLER: NO; MEMORY: NO
AA5 = T_POINT_R_0: Assy: DNI; COMPFIXED: NO; COMPGROUP: 0; COMPHEIGHT: 0.000; COMPKEY: NO; COMPLOC: [100.000,3500.000]; COMPLOCKED: NO; COMPROT: 0; COMPSIDE: TOP; DECOUPLER: NO; MEMORY: NO
AA6 = T_POINT_R_0: Assy: DNI; COMPFIXED: NO; COMPGROUP: 0; COMPHEIGHT: 0.000; COMPKEY: NO; COMPLOC: [100.000,3400.000]; COMPLOCKED: NO; COMPROT: 0; COMPSIDE: TOP; DECOUPLER: NO; MEMORY: NO
AA7 = T_POINT_R_0: Assy: DNI; COMPFIXED: NO; COMPGROUP: 0; COMPHEIGHT: 0.000; COMPKEY: NO; COMPLOC: [100.000,3300.000]; COMPLOCKED: NO; COMPROT: 0; COMPSIDE: TOP; DECOUPLER: NO; MEMORY: NO
AA8 = T_POINT_R_0: Assy: DNI; COMPFIXED: NO; COMPGROUP: 0; COMPHEIGHT: 0.000; COMPKEY: NO; COMPLOC: [100.000,3200.000]; COMPLOCKED: NO; COMPROT: 0; COMPSIDE: TOP; DECOUPLER: NO; MEMORY: NO
AA9 = T_POINT_R_0: Assy: DNI; COMPFIXED: NO; COMPGROUP: 0; COMPHEIGHT: 0.000; COMPKEY: NO; COMPLOC: [100.000,3100.000]; COMPLOCKED: NO; COMPROT: 0; COMPSIDE: TOP; DECOUPLER: NO; MEMORY: NO
AA10 = T_POINT_R_0: Assy: DNI; COMPFIXED: NO; COMPGROUP: 0; COMPHEIGHT: 0.000; COMPKEY: NO; COMPLOC: [100.000,3000.000]; COMPLOCKED: NO; COMPROT: 0; COMPSIDE: TOP; DECOUPLER: NO; MEMORY: NO
AA11 = T_POINT_R_0: Assy: DNI; COMPFIXED: NO; COMPGROUP: 0; COMPHEIGHT: 0.000; COMPKEY: NO; COMPLOC: [100.000,2900.000]; COMPLOCKED: NO; COMPROT: 0; COMPSIDE: TOP; DECOUPLER: NO; MEMORY: NO
AB1 AB2 = T_POINT_R_0: Assy: DNI; COMPFIXED: NO; COMPGROUP: 0; COMPHEIGHT: 0.000; COMPKEY: NO; COMPLOC: [200.000,3800.000]; COMPLOCKED: NO; COMPROT: 0; COMPSIDE: TOP; DECOUPLER: NO; MEMORY: NO
AB3 = T_POINT_R_0: Assy: DNI; COMPFIXED: NO; COMPGROUP: 0; COMPHEIGHT: 0.000; COMPKEY: NO; COMPLOC: [200.000,3700.000]; COMPLOCKED: NO; COMPROT: 0; COMPSIDE: TOP; DECOUPLER: NO; MEMORY: NO
AB4 = T_POINT_R_0: Assy: DNI; COMPFIXED: NO; COMPGROUP: 0; COMPHEIGHT: 0.000; COMPKEY: NO; COMPLOC: [200.000,3600.000]; COMPLOCKED: NO; COMPROT: 0; COMPSIDE: TOP; DECOUPLER: NO; MEMORY: NO
AB5 = T_POINT_R_0: Assy: DNI; COMPFIXED: NO; COMPGROUP: 0; COMPHEIGHT: 0.000; COMPKEY: NO; COMPLOC: [200.000,3500.000]; COMPLOCKED: NO; COMPROT: 0; COMPSIDE: TOP; DECOUPLER: NO; MEMORY: NO
AB6 = T_POINT_R_0: Assy: DNI; COMPFIXED: NO; COMPGROUP: 0; COMPHEIGHT: 0.000; COMPKEY: NO; COMPLOC: [200.000,3400.000]; COMPLOCKED: NO; COMPROT: 0; COMPSIDE: TOP; DECOUPLER: NO; MEMORY: NO
AB7 = T_POINT_R_0: Assy: DNI; COMPFIXED: NO; COMPGROUP: 0; COMPHEIGHT: 0.000; COMPKEY: NO; COMPLOC: [200.000,3300.000]; COMPLOCKED: NO; COMPROT: 0; COMPSIDE: TOP; DECOUPLER: NO; MEMORY: NO
AB8 = T_POINT_R_0: Assy: DNI; COMPFIXED: NO; COMPGROUP: 0; COMPHEIGHT: 0.000; COMPKEY: NO; COMPLOC: [200.000,3200.000]; COMPLOCKED: NO; COMPROT: 0; COMPSIDE: TOP; DECOUPLER: NO; MEMORY: NO
AB9 = T_POINT_R_0: Assy: DNI; COMPFIXED: NO; COMPGROUP: 0; COMPHEIGHT: 0.000; COMPKEY: NO; COMPLOC: [200.000,3100.000]; COMPLOCKED: NO; COMPROT: 0; COMPSIDE: TOP; DECOUPLER: NO; MEMORY: NO
AB10 = T_POINT_R_0: Assy: DNI; COMPFIXED: NO; COMPGROUP: 0; COMPHEIGHT: 0.000; COMPKEY: NO; COMPLOC: [200.000,3000.000]; COMPLOCKED: NO; COMPROT: 0; COMPSIDE: TOP; DECOUPLER: NO; MEMORY: NO
AB11 = T_POINT_R_0: Assy: DNI; COMPFIXED: NO; COMPGROUP: 0; COMPHEIGHT: 0.000; COMPKEY: NO; COMPLOC: [200.000,2900.000]; COMPLOCKED: NO; COMPROT: 0; COMPSIDE: TOP; DECOUPLER: NO; MEMORY: NO
AC1 AC2 = T_POINT_R_0: Assy: DNI; COMPFIXED: NO; COMPGROUP: 0; COMPHEIGHT: 0.000; COMPKEY: NO; COMPLOC: [300.000,3800.000]; COMPLOCKED: NO; COMPROT: 0; COMPSIDE: TOP; DECOUPLER: NO; MEMORY: NO
AC3 = T_POINT_R_0: Assy: DNI; COMPFIXED: NO; COMPGROUP: 0; COMPHEIGHT: 0.000; COMPKEY: NO; COMPLOC: [300.000,3700.000]; COMPLOCKED: NO; COMPROT: 0; COMPSIDE: TOP; DECOUPLER: NO; MEMORY: NO
AC4 = T_POINT_R_0: Assy: DNI; COMPFIXED: NO; COMPGROUP: 0; COMPHEIGHT: 0.000; COMPKEY: NO; COMPLOC: [300.000,3600.000]; COMPLOCKED: NO; COMPROT: 0; COMPSIDE: TOP; DECOUPLER: NO; MEMORY: NO
AC5 = T_POINT_R_0: Assy: DNI; COMPFIXED: NO; COMPGROUP: 0; COMPHEIGHT: 0.000; COMPKEY: NO; COMPLOC: [300.000,3500.000]; COMPLOCKED: NO; COMPROT: 0; COMPSIDE: TOP; DECOUPLER: NO; MEMORY: NO
AC6 = T_POINT_R_0: Assy: DNI; COMPFIXED: NO; COMPGROUP: 0; COMPHEIGHT: 0.000; COMPKEY: NO; COMPLOC: [300.000,3400.000]; COMPLOCKED: NO; COMPROT: 0; COMPSIDE: TOP; DECOUPLER: NO; MEMORY: NO
AC7 = T_POINT_R_0: Assy: DNI; COMPFIXED: NO; COMPGROUP: 0; COMPHEIGHT: 0.000; COMPKEY: NO; COMPLOC: [300.000,3300.000]; COMPLOCKED: NO; COMPROT: 0; COMPSIDE: TOP; DECOUPLER: NO; MEMORY: NO
AC8 = T_POINT_R_0: Assy: DNI; COMPFIXED: NO; COMPGROUP: 0; COMPHEIGHT: 0.000; COMPKEY: NO; COMPLOC: [300.000,3200.000]; COMPLOCKED: NO; COMPROT: 0; COMPSIDE: TOP; DECOUPLER: NO; MEMORY: NO
AC9 = T_POINT_R_0: Assy: DNI; COMPFIXED: NO; COMPGROUP: 0; COMPHEIGHT: 0.000; COMPKEY: NO; COMPLOC: [300.000,3100.000]; COMPLOCKED: NO; COMPROT: 0; COMPSIDE: TOP; DECOUPLER: NO; MEMORY: NO
AC10 = T_POINT_R_0: Assy: DNI; COMPFIXED: NO; COMPGROUP: 0; COMPHEIGHT: 0.000; COMPKEY: NO; COMPLOC: [300.000,3000.000]; COMPLOCKED: NO; COMPROT: 0; COMPSIDE: TOP; DECOUPLER: NO; MEMORY: NO
AC11 = T_POINT_R_0: Assy: DNI; COMPFIXED: NO; COMPGROUP: 0; COMPHEIGHT: 0.000; COMPKEY: NO; COMPLOC: [300.000,2900.000]; COMPLOCKED: NO; COMPROT: 0; COMPSIDE: TOP; DECOUPLER: NO; MEMORY: NO
AD1 AD2 = T_POINT_R_0: Assy: DNI; COMPFIXED: NO; COMPGROUP: 0; COMPHEIGHT: 0.000; COMPKEY: NO; COMPLOC: [400.000,3800.000]; COMPLOCKED: NO; COMPROT: 0; COMPSIDE: TOP; DECOUPLER: NO; MEMORY: NO
AD3 = T_POINT_R_0: Assy: DNI; COMPFIXED: NO; COMPGROUP: 0; COMPHEIGHT: 0.000; COMPKEY: NO; COMPLOC: [400.000,3700.000]; COMPLOCKED: NO; COMPROT: 0; COMPSIDE: TOP; DECOUPLER: NO; MEMORY: NO
AD4 = T_POINT_R_0: Assy: DNI; COMPFIXED: NO; COMPGROUP: 0; COMPHEIGHT: 0.000; COMPKEY: NO; COMPLOC: [400.000,3600.000]; COMPLOCKED: NO; COMPROT: 0; COMPSIDE: TOP; DECOUPLER: NO; MEMORY: NO
AD5 = T_POINT_R_0: Assy: DNI; COMPFIXED: NO; COMPGROUP: 0; COMPHEIGHT: 0.000; COMPKEY: NO; COMPLOC: [400.000,3500.000]; COMPLOCKED: NO; COMPROT: 0; COMPSIDE: TOP; DECOUPLER: NO; MEMORY: NO
AD6 = T_POINT_R_0: Assy: DNI; COMPFIXED: NO; COMPGROUP: 0; COMPHEIGHT: 0.000; COMPKEY: NO; COMPLOC: [400.000,3400.000]; COMPLOCKED: NO; COMPROT: 0; COMPSIDE: TOP; DECOUPLER: NO; MEMORY: NO
AD7 = T_POINT_R_0: Assy: DNI; COMPFIXED: NO; COMPGROUP: 0; COMPHEIGHT: 0.000; COMPKEY: NO; COMPLOC: [400.000,3300.000]; COMPLOCKED: NO; COMPROT: 0; COMPSIDE: TOP; DECOUPLER: NO; MEMORY: NO
AD8 = T_POINT_R_0: Assy: DNI; COMPFIXED: NO; COMPGROUP: 0; COMPHEIGHT: 0.000; COMPKEY: NO; COMPLOC: [400.000,3200.000]; COMPLOCKED: NO; COMPROT: 0; COMPSIDE: TOP; DECOUPLER: NO; MEMORY: NO
AD9 = T_POINT_R_0: Assy: DNI; COMPFIXED: NO; COMPGROUP: 0; COMPHEIGHT: 0.000; COMPKEY: NO; COMPLOC: [400.000,3100.000]; COMPLOCKED: NO; COMPROT: 0; COMPSIDE: TOP; DECOUPLER: NO; MEMORY: NO
AD10 = T_POINT_R_0: Assy: DNI; COMPFIXED: NO; COMPGROUP: 0; COMPHEIGHT: 0.000; COMPKEY: NO; COMPLOC: [400.000,3000.000]; COMPLOCKED: NO; COMPROT: 0; COMPSIDE: TOP; DECOUPLER: NO; MEMORY: NO
AD11 = T_POINT_R_0: Assy: DNI; COMPFIXED: NO; COMPGROUP: 0; COMPHEIGHT: 0.000; COMPKEY: NO; COMPLOC: [400.000,2900.000]; COMPLOCKED: NO; COMPROT: 0; COMPSIDE: TOP; DECOUPLER: NO; MEMORY: NO
AE1 AE2 = T_POINT_R_0: Assy: DNI; COMPFIXED: NO; COMPGROUP: 0; COMPHEIGHT: 0.000; COMPKEY: NO; COMPLOC: [500.000,3800.000]; COMPLOCKED: NO; COMPROT: 0; COMPSIDE: TOP; DECOUPLER: NO; MEMORY: NO
AE3 = T_POINT_R_0: Assy: DNI; COMPFIXED: NO; COMPGROUP: 0; COMPHEIGHT: 0.000; COMPKEY: NO; COMPLOC: [500.000,3700.000]; COMPLOCKED: NO; COMPROT: 0; COMPSIDE: TOP; DECOUPLER: NO; MEMORY: NO
AE4 = T_POINT_R_0: Assy: DNI; COMPFIXED: NO; COMPGROUP: 0; COMPHEIGHT: 0.000; COMPKEY: NO; COMPLOC: [500.000,3600.000]; COMPLOCKED: NO; COMPROT: 0; COMPSIDE: TOP; DECOUPLER: NO; MEMORY: NO
AE5 = T_POINT_R_0: Assy: DNI; COMPFIXED: NO; COMPGROUP: 0; COMPHEIGHT: 0.000; COMPKEY: NO; COMPLOC: [500.000,3500.000]; COMPLOCKED: NO; COMPROT: 0; COMPSIDE: TOP; DECOUPLER: NO; MEMORY: NO
AE6 = T_POINT_R_0: Assy: DNI; COMPFIXED: NO; COMPGROUP: 0; COMPHEIGHT: 0.000; COMPKEY: NO; COMPLOC: [500.000,3400.000]; COMPLOCKED: NO; COMPROT: 0; COMPSIDE: TOP; DECOUPLER: NO; MEMORY: NO
AE7 = T_POINT_R_0: Assy: DNI; COMPFIXED: NO; COMPGROUP: 0; COMPHEIGHT: 0.000; COMPKEY: NO; COMPLOC: [500.000,3300.000]; COMPLOCKED: NO; COMPROT: 0; COMPSIDE: TOP; DECOUPLER: NO; MEMORY: NO
AE8 = T_POINT_R_0: Assy: DNI; COMPFIXED: NO; COMPGROUP: 0; COMPHEIGHT: 0.000; COMPKEY: NO; COMPLOC: [500.000,3200.000]; COMPLOCKED: NO; COMPROT: 0; COMPSIDE: TOP; DECOUPLER: NO; MEMORY: NO
AE9 = T_POINT_R_0: Assy: DNI; COMPFIXED: NO; COMPGROUP: 0; COMPHEIGHT: 0.000; COMPKEY: NO; COMPLOC: [500.000,3100.000]; COMPLOCKED: NO; COMPROT: 0; COMPSIDE: TOP; DECOUPLER: NO; MEMORY: NO
AE10 = T_POINT_R_0: Assy: DNI; COMPFIXED: NO; COMPGROUP: 0; COMPHEIGHT: 0.000; COMPKEY: NO; COMPLOC: [500.000,3000.000]; COMPLOCKED: NO; COMPROT: 0; COMPSIDE: TOP; DECOUPLER: NO; MEMORY: NO
AE11 = T_POINT_R_0: Assy: DNI; COMPFIXED: NO; COMPGROUP: 0; COMPHEIGHT: 0.000; COMPKEY: NO; COMPLOC: [500.000,2900.000]; COMPLOCKED: NO; COMPROT: 0; COMPSIDE: TOP; DECOUPLER: NO; MEMORY: NO
AF1 AF2 = T_POINT_R_0: Assy: DNI; COMPFIXED: NO; COMPGROUP: 0; COMPHEIGHT: 0.000; COMPKEY: NO; COMPLOC: [600.000,3800.000]; COMPLOCKED: NO; COMPROT: 0; COMPSIDE: TOP; DECOUPLER: NO; MEMORY: NO
AF3 = T_POINT_R_0: Assy: DNI; COMPFIXED: NO; COMPGROUP: 0; COMPHEIGHT: 0.000; COMPKEY: NO; COMPLOC: [600.000,3700.000]; COMPLOCKED: NO; COMPROT: 0; COMPSIDE: TOP; DECOUPLER: NO; MEMORY: NO
AF4 = T_POINT_R_0: Assy: DNI; COMPFIXED: NO; COMPGROUP: 0; COMPHEIGHT: 0.000; COMPKEY: NO; COMPLOC: [600.000,3600.000]; COMPLOCKED: NO; COMPROT: 0; COMPSIDE: TOP; DECOUPLER: NO; MEMORY: NO
AF5 = T_POINT_R_0: Assy: DNI; COMPFIXED: NO; COMPGROUP: 0; COMPHEIGHT: 0.000; COMPKEY: NO; COMPLOC: [600.000,3500.000]; COMPLOCKED: NO; COMPROT: 0; COMPSIDE: TOP; DECOUPLER: NO; MEMORY: NO
AF6 = T_POINT_R_0: Assy: DNI; COMPFIXED: NO; COMPGROUP: 0; COMPHEIGHT: 0.000; COMPKEY: NO; COMPLOC: [600.000,3400.000]; COMPLOCKED: NO; COMPROT: 0; COMPSIDE: TOP; DECOUPLER: NO; MEMORY: NO
AF7 = T_POINT_R_0: Assy: DNI; COMPFIXED: NO; COMPGROUP: 0; COMPHEIGHT: 0.000; COMPKEY: NO; COMPLOC: [600.000,3300.000]; COMPLOCKED: NO; COMPROT: 0; COMPSIDE: TOP; DECOUPLER: NO; MEMORY: NO
AF8 = T_POINT_R_0: Assy: DNI; COMPFIXED: NO; COMPGROUP: 0; COMPHEIGHT: 0.000; COMPKEY: NO; COMPLOC: [600.000,3200.000]; COMPLOCKED: NO; COMPROT: 0; COMPSIDE: TOP; DECOUPLER: NO; MEMORY: NO
AF9 = T_POINT_R_0: Assy: DNI; COMPFIXED: NO; COMPGROUP: 0; COMPHEIGHT: 0.000; COMPKEY: NO; COMPLOC: [600.000,3100.000]; COMPLOCKED: NO; COMPROT: 0; COMPSIDE: TOP; DECOUPLER: NO; MEMORY: NO
AF10 = T_POINT_R_0: Assy: DNI; COMPFIXED: NO; COMPGROUP: 0; COMPHEIGHT: 0.000; COMPKEY: NO; COMPLOC: [600.000,3000.000]; COMPLOCKED: NO; COMPROT: 0; COMPSIDE: TOP; DECOUPLER: NO; MEMORY: NO
AF11 = T_POINT_R_0: Assy: DNI; COMPFIXED: NO; COMPGROUP: 0; COMPHEIGHT: 0.000; COMPKEY: NO; COMPLOC: [600.000,2900.000]; COMPLOCKED: NO; COMPROT: 0; COMPSIDE: TOP; DECOUPLER: NO; MEMORY: NO
AG1 AG8 = T_POINT_R_0: Assy: DNI; COMPFIXED: NO; COMPGROUP: 0; COMPHEIGHT: 0.000; COMPKEY: NO; COMPLOC: [700.000,3800.000]; COMPLOCKED: NO; COMPROT: 0; COMPSIDE: TOP; DECOUPLER: NO; MEMORY: NO
AG2 = T_POINT_R_0: Assy: DNI; COMPFIXED: NO; COMPGROUP: 0; COMPHEIGHT: 0.000; COMPKEY: NO; COMPLOC: [700.000,3100.000]; COMPLOCKED: NO; COMPROT: 0; COMPSIDE: TOP; DECOUPLER: NO; MEMORY: NO
AG3 = T_POINT_R_0: Assy: DNI; COMPFIXED: NO; COMPGROUP: 0; COMPHEIGHT: 0.000; COMPKEY: NO; COMPLOC: [700.000,3400.000]; COMPLOCKED: NO; COMPROT: 0; COMPSIDE: TOP; DECOUPLER: NO; MEMORY: NO
AG4 = T_POINT_R_0: Assy: DNI; COMPFIXED: NO; COMPGROUP: 0; COMPHEIGHT: 0.000; COMPKEY: NO; COMPLOC: [700.000,3300.000]; COMPLOCKED: NO; COMPROT: 0; COMPSIDE: TOP; DECOUPLER: NO; MEMORY: NO
AG5 = T_POINT_R_0: Assy: DNI; COMPFIXED: NO; COMPGROUP: 0; COMPHEIGHT: 0.000; COMPKEY: NO; COMPLOC: [700.000,3200.000]; COMPLOCKED: NO; COMPROT: 0; COMPSIDE: TOP; DECOUPLER: NO; MEMORY: NO
AG6 = T_POINT_R_0: Assy: DNI; COMPFIXED: NO; COMPGROUP: 0; COMPHEIGHT: 0.000; COMPKEY: NO; COMPLOC: [700.000,3000.000]; COMPLOCKED: NO; COMPROT: 0; COMPSIDE: TOP; DECOUPLER: NO; MEMORY: NO
AG7 = T_POINT_R_0: Assy: DNI; COMPFIXED: NO; COMPGROUP: 0; COMPHEIGHT: 0.000; COMPKEY: NO; COMPLOC: [700.000,2900.000]; COMPLOCKED: NO; COMPROT: 0; COMPSIDE: TOP; DECOUPLER: NO; MEMORY: NO
AG9 = T_POINT_R_0: Assy: DNI; COMPFIXED: NO; COMPGROUP: 0; COMPHEIGHT: 0.000; COMPKEY: NO; COMPLOC: [700.000,3600.000]; COMPLOCKED: NO; COMPROT: 0; COMPSIDE: TOP; DECOUPLER: NO; MEMORY: NO
AG10 = T_POINT_R_0: Assy: DNI; COMPFIXED: NO; COMPGROUP: 0; COMPHEIGHT: 0.000; COMPKEY: NO; COMPLOC: [700.000,3700.000]; COMPLOCKED: NO; COMPROT: 0; COMPSIDE: TOP; DECOUPLER: NO; MEMORY: NO
AG11 = T_POINT_R_0: Assy: DNI; COMPFIXED: NO; COMPGROUP: 0; COMPHEIGHT: 0.000; COMPKEY: NO; COMPLOC: [700.000,3500.000]; COMPLOCKED: NO; COMPROT: 0; COMPSIDE: TOP; DECOUPLER: NO; MEMORY: NO
C40 = 0u1_0402: CAP CECAP CER 10UF 10V X5R 20% 0603; Manufacturer: Taiyo Yuden; Manufacturer Part Number: LMK107BJ106MALTD
JP1-JP4 = JUMPER_0
JP5 = Receptacle_20X2
R35-R40 = 0R_0603: RES 0.0 OHM 1/10W JUMP 0603 SMD; Assy: DNI
U3 = LIFCL-40-BG400: Color: Default; Location X-Coordinate: 0; Location Y-Coordinate: 0; Power Pins Visible: False; Primitive: DEFAULT; SPLIT_INST: TRUE; SWAP_INFO: (S1+S2+S3+S4+S5+S6+S7+S8+S9+S10+S11+S12+S13+S14+S15)
C43 C45 C51 = CAP_CER_100nF_0402_10V: CAP CER 0.1UF 10V X7R 0402; MFG: Wurth; MFG P/N: 885012205018; Manufacturer: Wurth; Manufacturer Part Number: 885012205018
C44 C46 C47 C49 C50 C52-C55 C57 = CAP_CER_100nF_0402_10V: CAP CER 0.1UF 25V 10% X5R 0201; Manufacturer: Murata; Manufacturer Part Number: GRM033R61E104KE14J
C48 C56 = CAP_SMT_0805
FB1-FB3 = INDUCTOR_1: FERRITE BEAD 120 OHM 0402 1LN; Manufacturer: TDK Corporation
J10-J12 J14-J16 = RCA_JACK_0: Assy: DNI
J13 = CON3: 3 Positions Header, Unshrouded Connector 0.100" (2.54mm) Through Hole Gold; Manufacturer: Wurth; PART_NUMBER: 61300311121
L1-L3 L10 L11 = FB0603: FERRITE CHIP 600 OHM 500MA 0603
R18 R19 R45 = RESISTOR: Populate: <Populate>
R46 R49 R54-R56 R58 R60 R63 = RES_10K_1W16_0402_5P: RES SMD 0.0OHM JUMPER 1/10W 0402; Digikey P/N: RMCF0603JT10K0TR-ND; MFG: Panasonic; MFG P/N: ERJ-2GE0R00X; Manufacturer: Panasonic; Manufacturer Part Number: ERJ-2GE0R00X; Wattage: 1/10W
R47 R48 R51 R52 R57 R59 R61 R64 = 0R_0603: RES SMD 0.0OHM JUMPER 1/10W 0402; Assy: DNI; MFG: Panasonic; MFG P/N: ERJ-2GE0R00X; Manufacturer: Panasonic; Manufacturer Part Number: ERJ-2GE0R00X
R50 R62 = R
R65 R66 = RES_10K_1W16_0402_5P: RES SMD 0.0OHM JUMPER 1/10W 0402; Assy: DNI; Digikey P/N: RMCF0603JT10K0TR-ND; MFG: Panasonic; MFG P/N: ERJ-2GE0R00X; Manufacturer: Panasonic; Manufacturer Part Number: ERJ-2GE0R00X; Wattage: 1/10W
RN1 = EXB2HV472JV: RESVALUE: 4_7K
SW1 = SW_DIP-8: SWITCH SLIDE DIP SPST 100MA 20V; Manufacturer: CTS Electrocomponents; Populate: <Populate>
TP1-TP5 TP_V1P0_VCCSD TP_V1P8_VCCAUXSD TP_V1P8_VCCPLLSD = TP_S_40_63: Assy: DNI
U4 = AK5DAF1-125.0000T2
U5 = AK5DAF1-200.0000T2
C5 C6 C10 C14 = C: Populate: <Populate>
C16 C17 = 0u1_0402: CAP CER 18PF 25V 10% NP0 0402; Digikey P/N: C0402C180K3GACTU-ND; Manufacturer Part Number: C0402C180K3GACTU
D2 = ESDR0502
J1 = header1x8_100: CONN HEADER 8POS .100 VERT TIN; Assy: DNI; Digikey P/N: WM50017-08-ND; Manufacturer Part Number: 0022284081
J2 = USB_MINI_B_0: CONN RCPT USB2.0 MINI B SMD R/A; COMPFIXED: NO; COMPGROUP: 0; COMPHEIGHT: 0.000; COMPKEY: NO; COMPLOC: [370.000,2590.000]; COMPLOCKED: NO; COMPROT: 270; COMPSIDE: TOP; DECOUPLER: NO; FPLIST: TYPE_B; MEMORY: NO; Manufacturer: TE Connectivity AMP Connectors; Manufacturer Part Number: 1734035-2; Part Number: 1734035-2; Populate: <Populate>
R1-R3 = 5k1_0402: RES 4.70K OHM 1/10W 1% 0603 SMD; Digikey P/N: 541-4.70KHTR-ND; Manufacturer: Vishay; Manufacturer Part Number: CRCW06034K70FKEA
R4 R9 = 5k1_0402: Digikey P/N: 541-2.20KHTR-ND; Manufacturer: Vishay; Manufacturer Part Number: CRCW06032K20FKEA
R5 = 0R_0603: RES SMD 33 OHM 1% 1/10W 0402; Manufacturer: Panasonic; Manufacturer Part Number: ERJ-2RKF33R0X
R6-R8 R20-R22 = 0R_0603: RES 0.0 OHM 1/10W JUMP 0603 SMD
R10-R12 = RES_10K_1W16_0402_5P: RES 10K OHM 1/10W 5% 0603; Digikey P/N: RMCF0603JT10K0TR-ND; Manufacturer: Stackpole Electronics Inc; Manufacturer Part Number: RMCF0603JT10K0; Wattage: 1/10W
R13 R16 = 10k_0402: RES 12K OHM 1/10W 1% 0603 SMD; Digikey P/N: 311-12.0KHRTR-ND; Manufacturer Part Number: RC0603FR-0712KL; Tolerance: 1%
R14 = RES_0
R15 R17 = 0R_0603: Assy: DNI
R172 = 5k1_0402: RES SMD 10K OHM 1% 1/10W 0603; Digikey P/N: 541-4.70KHTR-ND; Manufacturer: Yageo; Manufacturer Part Number: RC0603FR-0710KL
R173 = 0R_0603: RES SMD 1K OHM 1% 1/10W 0603; Assy: DNI; Manufacturer Part Number: RC0603FR-071KL
U1 = FT2232HL: IC USB HS DUAL UART/FIFO 64-LQFP; Assy: Customer Supplied
U2 = 93LC56_SO8_0: IC EEPROM 2KBIT 3MHZ 8SOIC
X1 = crystal-3p2x2p5: CRYSTAL 12MHZ 18PF SMD

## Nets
GND: AA11.1(TP) AB11.1(TP) AC11.1(TP) AD11.1(TP) AE11.1(TP) AF11.1(TP) AG11.1(TP) C1.2 C2.2 C3.2 C4.2 C5.1 C6.1 C7.2 C8.2 C9.2 C10.1 C11.2 C12.2 C13.2 C14.1 C15.2 C16.1 C17.1 C18.2 C19.2 C20.2 C21.2 C22.2 C23.2 C24.2 C25.2 C26.2 C27.2 C28.2 C29.2 C30.2 C31.2 C32.2 C33.2 C34.2 C35.2 C36.2 C37.2 C38.2 C39.2 C40.2 C41.2 C42.2 C45.1 C46.1 C47.1 C48.2 C49.1 C56.2 C57.1 C58.2 C59.2 C60.2 C61.2 C62.2 C63.2 C64.2 C65.2 C66.2 C67.2 C68.2 C69.2 C70.2 C71.2 C72.2 C73.2 CN1.4(DGND1) CN1.7(DGND2) CN1.10(DGND3) CN1.13(DGND4) CN1.16(DGND5) CN1.17(DGND6) CN1.27(DGND7) CN1.28(DGND8) CN1.30(DGND9) D2.1(GND) J1.7 J2.5(GND) J2.6(CASE) J2.7(CASE) J2.8(CASE) J2.9(CASE) J6.1 J6.2 J6.5 J6.6 J6.9 J6.10 J6.13 J6.14 J6.17 J6.18 J10.2(SHIELD1) J10.3(SHIELD2) J10.4(SHIELD3) J10.5(SHIELD4) J11.2(SHIELD1) J11.3(SHIELD2) J11.4(SHIELD3) J11.5(SHIELD4) J12.2(SHIELD1) J12.3(SHIELD2) J12.4(SHIELD3) J12.5(SHIELD4) J13.2 J14.2(SHIELD1) J14.3(SHIELD2) J14.4(SHIELD3) J14.5(SHIELD4) J15.2(SHIELD1) J15.3(SHIELD2) J15.4(SHIELD3) J15.5(SHIELD4) J16.2(SHIELD1) J16.3(SHIELD2) J16.4(SHIELD3) J16.5(SHIELD4) J17.5 J17.11 J18.5 J18.11 J19.5 J19.11 JP1.2 JP5.6 JP5.9 JP5.14 JP5.20 JP5.25 JP5.30 JP5.34 JP5.39 R4.2 R13.1 SW1.1(A1) SW1.2(A2) SW1.3(A3) SW1.4(A4) SW1.5(A5) SW1.6(A6) SW1.7(A7) SW1.8(A8) SW2.2 SW2.4 SW3.2 SW3.4 SW4.2 SW4.4 U1.1(GND) U1.5(GND) U1.10(AGND) U1.11(GND) U1.13(TEST) U1.15(GND) U1.25(GND) U1.35(GND) U1.47(GND) U1.51(GND) U2.5(VSS) U4.3(GND) U5.3(GND) X1.2(G1) X1.4(G2) X2.2(GND) ; also on sheet 9 10 11 12 13
V1P0_LDO: FB2.2 L6.2 L7.2 L8.2 L9.2 ; also on sheet 11 13
V1P2: C19.1 C22.1 CN1.25(DVDD1V2) ; also on sheet 11
V1P8: AA1.1(TP) AB1.1(TP) AC1.1(TP) AD1.1(TP) AE1.1(TP) AF1.1(TP) AG1.1(TP) C20.1 C23.1 C24.1 CN1.26(DVDD1V8) R23.2 X2.4(VDD) ; also on sheet 11 13
V1P8_LDO: FB1.2 FB3.2 L4.2 L5.2 ; also on sheet 9 11 12 13
V2P8: C18.1 C21.1 CN1.18(AF_VDD2V8) CN1.29(AVDD2V8) ; also on sheet 11
V3P3: AA2.1(TP) AB2.1(TP) AC2.1(TP) AD2.1(TP) AE2.1(TP) AF2.1(TP) AG2.1(TP) C1.1 C2.1 C3.1 C4.1 C5.2 C15.1 JP3.1 L1.2 L3.2 L10.2 L11.2 R9.2 R10.1 R11.1 R12.1 U1.20(VCCIO) U1.31(VCCIO) U1.42(VCCIO) U1.50(VREGIN) U1.56(VCCIO) U2.6(ORG) U2.8(VCC) ; also on sheet 9 10 11 13
V5P0: JP4.1 ; also on sheet 11 13
VBUS: J2.1(VCC) L2.2
VBUS_5V: C8.1 D2.6(VBUS) L2.1
VCC1_8FT: C11.1 C12.1 C13.1 C14.2 U1.12(VCORE) U1.37(VCORE) U1.49(VREGOUT) U1.64(VCORE)
VCCIO0: R172.1 ; also on sheet 9 11
VCCIO1: C64.1 C65.1 C66.1 J1.1 R1.1 R2.1 R3.1 R14.2 R18.2 R19.2 R67.1 R68.1 R69.1 R75.2 R174.2 R175.2 R176.2 R177.2 R178.2 R179.2 R180.2 R181.2 U3.G17(VCCIO1) U3.J18(VCCIO1) ; also on sheet 11
VCCIO2: C58.1 C59.1 C60.1 R182.2 R183.2 R184.2 R185.2 R186.2 R187.2 RN1.9 RN1.10(9) RN1.11(9) RN1.12(9) RN1.13(9) RN1.14(9) RN1.15(9) RN1.16(9) U3.N17(VCCIO2) U3.U19(VCCIO2) ; also on sheet 10 11
VCCIO5: R25.1 R26.1 ; also on sheet 10 11
VCCIO6: C39.1 C40.1 C41.1 C42.1 U3.L3(VCCIO6) U3.P3(VCCIO6) ; also on sheet 11
VCCIO7: C67.1 C68.1 C69.1 C70.1 C71.1 C72.1 C73.1 J17.6 J17.12 J18.6 J18.12 J19.6 J19.12 U3.E5(VCCIO7) U3.H3(VCCIO7) ; also on sheet 11
6_inch_long_trace: TP4.1(TP) U3.V18(PR47A) U3.V19(PR47B)
10_inch_long_trace: TP5.1(TP) U3.W19(PR49A) U3.Y19(PR49B)
12MHz: JP2.2 U3.L13(PR17A/PCLKT1_2)
125MHz: R54.1 U4.4(OP)
125MHz_N: R56.1 U4.5(ON)
200MHz: R65.1 U5.4(OP)
200MHz_N: R66.1 U5.5(ON)
ADBUS0: R5.1 U1.16(ADBUS0)
ADBUS1: R6.1 U1.17(ADBUS1)
ADBUS2: R7.1 U1.18(ADBUS2)
ADBUS3: R8.1 U1.19(ADBUS3)
CAM0_0N: CN1.11(DATA0_N) R28.2 U3.C1(DPHY0_DN0)
CAM0_0P: CN1.12(DATA0_P) R28.1 U3.B2(DPHY0_DP0)
CAM0_1N: CN1.8(DATA1_N) R29.2 U3.B3(DPHY0_DN1)
CAM0_1P: CN1.9(DATA1_P) R29.1 U3.A3(DPHY0_DP1)
CAM0_2N: CN1.14(DATA2_N) R30.2 U3.D1(DPHY0_DN2)
CAM0_2P: CN1.15(DATA2_P) R30.1 U3.C2(DPHY0_DP2)
CAM0_3N: CN1.5(DATA3_N) R31.2 U3.B4(DPHY0_DN3)
CAM0_3P: CN1.6(DATA3_P) R31.1 U3.A4(DPHY0_DP3)
CAM0_CLKN: CN1.2(CLK_N) R27.2 U3.B1(DPHY0_CKN)
CAM0_CLKP: CN1.3(CLK_P) R27.1 U3.A2(DPHY0_CKP)
CAM0_MCLK: CN1.20(MCLK) R24.2
CAM_RESET: CN1.24(XCLR) ; also on sheet 10
CAM_SCL: CN1.23(SCL) R26.2 ; also on sheet 10
CAM_SDA: CN1.22(SDA) R25.2 ; also on sheet 10
DM: D2.3(NC3) D2.4(D-) J2.2(D-) U1.7(DM)
DP: D2.2(NC2) D2.5(D+) J2.3(D+) U1.8(DP)
DPHY1_CKN: J6.4 U3.B8(DPHY1_CKN)
DPHY1_CKP: J6.3 U3.A8(DPHY1_CKP)
DPHY1_DN0: J6.8 U3.B7(DPHY1_DN0)
DPHY1_DN1: J6.12 U3.B9(DPHY1_DN1)
DPHY1_DN2: J6.16 U3.B6(DPHY1_DN2)
DPHY1_DN3: J6.20 U3.B10(DPHY1_DN3)
DPHY1_DP0: J6.7 U3.A7(DPHY1_DP0)
DPHY1_DP1: J6.11 U3.A9(DPHY1_DP1)
DPHY1_DP2: J6.15 U3.A6(DPHY1_DP2)
DPHY1_DP3: J6.19 U3.A10(DPHY1_DP3)
FMC_PRSNT: U3.N20(PR34B) ; also on sheet 10
FMC_SCL: U3.M20(PR32B) ; also on sheet 10
FMC_SDA: U3.M19(PR32A/PCLKT2_1) ; also on sheet 10
FMC_TCK: U3.P19(PR36A) ; also on sheet 10
FMC_TDI: U3.P20(PR36B) ; also on sheet 10
FMC_TDO: U3.P17(PR38A) ; also on sheet 10
FMC_TMS: U3.P18(PR38B) ; also on sheet 10
FT_EECLK: R11.2 U1.62(EECLK) U2.2(CLK)
FT_EECS: R10.2 U1.63(EECS) U2.1(CS)
FT_EEDATA: R16.1 U1.61(EEDATA) U2.3(DI)
FT_OSCI: C16.2 U1.2(OSCI) X1.1
FT_OSCO: C17.2 JP2.1 U1.3(OSCO) X1.3
FT_REF: R13.2 U1.6(REF)
FT_RSTb: JP1.1 R9.1 U1.14(RESET#)
FT_VPHY: C9.1 C10.2 L3.1 U1.4(VPHY)
FT_VPLL: C6.2 C7.1 L1.1 U1.9(VPLL)
GSRN: C63.1 R72.2 TP7.1(TP) U3.G19(PR13B/PMU_WAKEUP)
LED0: D3.1(CATHODE) U3.E17(PR3B)
LED1: D4.1(CATHODE) U3.F13(PR4A)
LED2: D5.1(CATHODE) U3.G13(PR4B)
LED3: D6.1(CATHODE) U3.F14(PR6A)
LED4: D7.1(CATHODE) U3.L16(PR19A/PCLKT1_1)
LED5: D8.1(CATHODE) U3.L15(PR19B)
LED6: D9.1(CATHODE) U3.L20(PR20A/PCLKT1_0)
LED7: D10.1(CATHODE) U3.L19(PR20B)
LED8: D11.1(CATHODE) U3.R17(PR40A)
LED9: D12.1(CATHODE) U3.R18(PR40B)
LED10: D13.1(CATHODE) U3.U20(PR42A)
LED11: D14.1(CATHODE) U3.T20(PR42B)
LED12: D15.1(CATHODE) U3.W20(PR44A)
LED13: D16.1(CATHODE) U3.V20(PR44B)
OSCN: R49.2 R56.2 R66.2
OSCP: R46.2 R54.2 R65.2
PMOD0_1: J17.1 U3.D10(PL3A/ULC_GPLL0T_IN)
PMOD0_2: J17.2 U3.D9(PL3B/ULC_GPLL0C_IN)
PMOD0_3: J17.3 U3.D7(PL4A)
PMOD0_4: J17.4 U3.D8(PL4B)
PMOD0_7: J17.7 U3.D6(PL6A)
PMOD0_8: J17.8 U3.D5(PL6B)
PMOD0_9: J17.9 U3.D4(PL8A)
PMOD0_10: J17.10 U3.D3(PL8B)
PMOD1_1: J18.1 U3.E10(PL10A)
PMOD1_2: J18.2 U3.E9(PL10B)
PMOD1_3: J18.3 U3.E7(PL11A)
PMOD1_4: J18.4 U3.E8(PL11B)
PMOD1_7: J18.7 U3.E4(PL13A)
PMOD1_8: J18.8 U3.E3(PL13B)
PMOD1_9: J18.9 U3.E2(PL15A)
PMOD1_10: J18.10 U3.F1(PL15B)
PMOD2_1: J19.1 U3.J2(PL17A/PCLKT7_2)
PMOD2_2: J19.2 U3.J1(PL17B)
PMOD2_3: J19.3 U3.K2(PL19A/PCLKT7_1)
PMOD2_4: J19.4 U3.K1(PL19B)
PMOD2_7: J19.7 U3.K3(PL20A/PCLKT7_0)
PMOD2_8: J19.8 U3.K4(PL20B)
PMOD2_9: J19.9 ; also on sheet 9
PMOD2_10: J19.10 ; also on sheet 9
PROGRAMN: R172.2 R173.2 ; also on sheet 9
PS_POR_B: U3.N19(PR34A/PCLKT2_2) ; also on sheet 10
PUSHBUTTON0: C61.1 R70.1 TP6.1(TP) U3.G14(PR15A)
PUSHBUTTON1: C62.1 R71.1 TP8.1(TP) U3.G15(PR15B)
R_ext: R45.1 U3.C14(SD0_REXT)
RASP_5V: C37.1 JP4.2 JP5.2 JP5.4
RASP_ID_SC: JP5.28 R39.1 U3.M4(PL36A)
RASP_ID_SD: JP5.27 R40.1 U3.M7(PL38B)
RASP_IO02: JP5.3 U3.L6(PL30B)
RASP_IO03: JP5.5 U3.L5(PL30A/PCLKT6_0)
RASP_IO04: JP5.7 U3.M3(PL34B)
RASP_IO05: JP5.29 U3.K8(PL26B)
RASP_IO06: JP5.31 U3.L7(PL32A/PCLKT6_1)
RASP_IO07: JP5.26 U3.N5(PL40B)
RASP_IO08: JP5.24 U3.P6(PL46B)
RASP_IO09: JP5.21 U3.K6(PL24B)
RASP_IO10: JP5.19 U3.N4(PL40A)
RASP_IO11: JP5.23 U3.N7(PL42B)
RASP_IO12: JP5.32 U3.L8(PL32B)
RASP_IO13: JP5.33 U3.M5(PL36B)
RASP_IO14: JP5.8 R35.2 U3.M2(PL34A/PCLKT6_2)
RASP_IO15: JP5.10 R36.2 U3.L1(PL27A)
RASP_IO16: JP5.36 U3.N6(PL42A)
RASP_IO17: JP5.11 R38.2 U3.L2(PL27B)
RASP_IO18: JP5.12 R37.2 U3.R2(PL47B)
RASP_IO19: JP5.35 U3.M6(PL38A)
RASP_IO20: JP5.38 U3.R3(PL49A)
RASP_IO21: JP5.40 U3.R4(PL49B)
RASP_IO22: JP5.15 U3.P2(PL44B)
RASP_IO23: JP5.16 U3.P1(PL44A)
RASP_IO24: JP5.18 U3.K7(PL26A)
RASP_IO25: JP5.22 U3.K5(PL24A)
RASP_IO26: JP5.37 U3.P5(PL46A)
RASP_IO27: JP5.13 U3.R1(PL47A)
Ref_return_pll: C43.1 C44.1 C51.1 C52.1 R45.2 U3.B14(SD0_REFRET)
REFCLKN: R43.1 R49.1 R51.1 R52.1 U3.C11(SD0_REFCLKN)
REFCLKN_FMC: R52.2 ; also on sheet 10
REFCLKN_SMA: J14.1(CENTER) R51.2
REFCLKP: R43.2 R46.1 R47.1 R48.1 U3.C12(SD0_REFCLKP)
REFCLKP_FMC: R48.2 ; also on sheet 10
REFCLKP_SMA: J10.1(CENTER) R47.2
RXD_UART: R17.2 U3.F18(PR10A)
RXDN: C53.1 R58.1 R59.1
RXDN_FMC: R59.2 ; also on sheet 10
RXDN_SMA: J15.1(CENTER) R58.2
RXDNF: C53.2 R41.1 U3.A15(SD0_RXDN)
RXDP: C50.1 R55.1 R57.1
RXDP_FMC: R57.2 ; also on sheet 10
RXDP_SMA: J11.1(CENTER) R55.2
RXDPF: C50.2 R41.2 U3.A16(SD0_RXDP)
SCL: R20.2 R39.2 R74.1 TP1.1(TP)
SDA: R21.2 R22.2 R40.2 R73.1 TP2.1(TP)
short_stub_trace: TP3.1(TP) U3.T18(PR46A) U3.U18(PR46B)
SWITCH0: RN1.8 SW1.16(B1) U3.N14(PR24A)
SWITCH1: RN1.1(8) SW1.15(B2) U3.M14(PR24B)
SWITCH2: RN1.5(8) SW1.14(B3) U3.M16(PR26A)
SWITCH3: RN1.2(8) SW1.13(B4) U3.M15(PR26B)
SWITCH4: RN1.7(8) SW1.12(B5) U3.N15(PR27A)
SWITCH5: RN1.6(8) SW1.11(B6) U3.N16(PR27B)
SWITCH6: RN1.3(8) SW1.10(B7) U3.M17(PR30A/PCLKT2_0)
SWITCH7: RN1.4(8) SW1.9(B8) U3.M18(PR30B)
TCK: J1.8 R4.1 R5.2 R35.1 U3.G18(PR13A/TCK/SCLK/PMU_EXT_CLK)
TDI: J1.3 R2.2 R6.2 R38.1 U3.F17(PR8B/TDI/SSI)
TDO: J1.2 R3.2 R7.2 R36.1 U3.F19(PR10B/TDO/SSO)
TMS: J1.6 R1.2 R8.2 R37.1 U3.F15(PR6B/TMS/SCSN)
TXD_UART: R15.2 U3.F16(PR8A)
TXDN: C55.1 R63.1 R64.1
TXDN_FMC: R64.2 ; also on sheet 10
TXDN_SMA: J16.1(CENTER) R63.2
TXDNF: C55.2 U3.A12(SD0_TXDN)
TXDP: C54.1 R60.1 R61.1
TXDP_FMC: R61.2 ; also on sheet 10
TXDP_SMA: J12.1(CENTER) R60.2
TXDPF: C54.2 U3.A13(SD0_TXDP)
UART_ACT: D1.1(CATHODE) R17.1 R18.1 R21.1 U1.39(BDBUS1)
N02138: R12.2 R16.2 U2.4(DO)
N06990: C38.1 JP3.2 JP5.1 JP5.17
N16616563: C56.1 C57.2 L11.1 R62.2 U5.6(VCC)
N16616747: J13.1 R62.1 U5.1(OE)
N16632070: R15.1 R19.1 R20.1 U1.38(BDBUS0)
N16632104: R22.1 U1.40(BDBUS2)
N17051987: C27.1 C28.1 J3.1 R32.1 U3.D2(VCCADPHY0)
N17052185: C33.1 C34.1 J4.1 R33.1 U3.B5(VCCPLLDPHY0)
N17052239: C35.1 C36.1 J5.1 R34.1 U3.C4(VCCDPHY0)
N17055174: R75.1 U3.E19(JTAG_EN/JTAG)
N17055619: R67.2 R70.2 SW2.1 SW2.3
N17055696: R68.2 R71.2 SW3.1 SW3.3
N17070358: FB1.1 J7.1 R42.1
N17070375: C43.2 C44.2 J7.2 R42.2 TP_V1P8_VCCPLLSD.1(TP) U3.C13(VCCPLLSD0)
N17094496: R23.1 X2.1(STDBY#)
N17094502: R24.1 X2.3(OUT)
N17109649: C25.1 C26.1 L4.1 U3.C7(VCCADPHY1)
N17109693: C29.1 C30.1 L6.1 U3.C9(VCCPLLDPHY1)
N17109747: C31.1 C32.1 L8.1 U3.C5(VCCDPHY1)
N17200489: R69.2 R72.1 SW4.1 SW4.3
N17232620: D11.2(ANODE) R182.1
N17232622: D12.2(ANODE) R183.1
N17232650: D13.2(ANODE) R184.1
N17232670: D14.2(ANODE) R185.1
N17232716: D15.2(ANODE) R186.1
N17232718: D16.2(ANODE) R187.1
N17274099: D9.2(ANODE) R180.1
N17274101: D7.2(ANODE) R178.1
N17274103: D10.2(ANODE) R181.1
N17274105: D8.2(ANODE) R179.1
N17274184: D3.2(ANODE) R174.1
N17274186: D4.2(ANODE) R175.1
N17274224: D5.2(ANODE) R176.1
N17274244: D6.2(ANODE) R177.1
N17274753: R73.2 U3.E20(PR11A/SDA)
N17274811: R74.2 U3.F20(PR11B/SCL)
N17329427: J3.2 L5.1 R32.2
N17329480: J4.2 L7.1 R33.2
N17329573: J5.2 L9.1 R34.2
N17423319: TP9.1(TP) U3.L14(PR17B)
N17431307: C51.2 C52.2 J9.2 R53.2 TP_V1P8_VCCAUXSD.1(TP) U3.B11(VCCAUXSD)
N17431309: FB3.1 J9.1 R53.1
N17433122: C45.2 C46.2 C47.2 J8.2 R44.2 TP_V1P0_VCCSD.1(TP) U3.B13(VCCSD0_2) U3.B15(VCCSD0_1)
N17433124: FB2.1 J8.1 R44.1
N17501322: C48.1 C49.2 L10.1 R50.2 U4.6(VCC)
N17501372: J13.3 R50.1 U4.1(OE)
N17591276: R173.1 U1.24(ADBUS7)
N17715075: D1.2(ANODE) R14.1

Not connected (* = marked no-connect by the designer): AA3 1(TP); AA4 1(TP); AA5 1(TP); AA6 1(TP); AA7 1(TP); AA8 1(TP); AA9 1(TP); AA10 1(TP); AB3 1(TP); AB4 1(TP); AB5 1(TP); AB6 1(TP); AB7 1(TP); AB8 1(TP); AB9 1(TP); AB10 1(TP); AC3 1(TP); AC4 1(TP); AC5 1(TP); AC6 1(TP); AC7 1(TP); AC8 1(TP); AC9 1(TP); AC10 1(TP); AD3 1(TP); AD4 1(TP); AD5 1(TP); AD6 1(TP); AD7 1(TP); AD8 1(TP); AD9 1(TP); AD10 1(TP); AE3 1(TP); AE4 1(TP); AE5 1(TP); AE6 1(TP); AE7 1(TP); AE8 1(TP); AE9 1(TP); AE10 1(TP); AF3 1(TP); AF4 1(TP); AF5 1(TP); AF6 1(TP); AF7 1(TP); AF8 1(TP); AF9 1(TP); AF10 1(TP); AG3 1(TP); AG4 1(TP); AG5 1(TP); AG6 1(TP); AG7 1(TP); AG8 1(TP); AG9 1(TP); AG10 1(TP); CN1 1(NC1)* 19(NC2)* 21(SYNC)*; J1 4* 5*; J2 4(NC)*; U1 21(ADBUS4)* 22(ADBUS5)* 23(ADBUS6)* 26(ACBUS0) 27(ACBUS1)* 28(ACBUS2)* 29(ACBUS3)* 30(ACBUS4)* 32(ACBUS5)* 33(ACBUS6)* 34(ACBUS7)* 36(SUSPEND#)* 41(BDBUS3) 43(BDBUS4) 44(BDBUS5) 45(BDBUS6) 46(BDBUS7) 48(BCBUS0)* 52(BCBUS1)* 53(BCBUS2)* 54(BCBUS3)* 55(BCBUS4)* 57(BCBUS5)* 58(BCBUS6)* 59(BCBUS7)* 60(PWREN#)*; U2 7(NU)*; U3 F2(NC65) F3(NC64) F4(NC51) F5(NC50) F6(NC49) F7(NC48) F8(NC61) G1(NC53) G2(NC52) G3(NC70) G4(NC67) G5(NC66) G6(NC60) G7(NC59) G8(NC54) G20(NC1) H1(NC63) H2(NC62) H5(NC58) H6(NC57) H7(NC56) H8(NC55) H13(NC2) H14(NC3) H15(NC4) H16(NC13) H17(NC18) H18(NC25) H19(NC16) H20(NC17) J3(NC74) J4(NC73) J5(NC72) J6(NC71) J7(NC69) J8(NC68) J13(NC10) J14(NC12) J15(NC5) J16(NC6) J19(NC7) J20(NC8) K13(NC9) K14(NC11) K15(NC14) K16(NC15) K17(NC19) K18(NC20) K19(NC21) K20(NC22) L17(NC24) L18(NC23) M1(NC47) N1(NC46) N2(NC45) N3(NC44) P15(NC29) P16(NC28) R19(NC27) R20(NC26); U4 2(NC)*; U5 2(NC)*

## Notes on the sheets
sheet 1
- CrossLink-NX  Evaluation Board
- Rev - B
- 01 - Title page
  02 - Block Diagram
  03 - USB Interface
  04 - Camera Interface (DPHYs)
  05 - Raspberry Pi and User I/O Interface (Bank6)
  06 - SERDES SMAs / Switches / FMC Control  (Bank2)
  07 - I2C LEDs and Push Buttons (Bank1)
  08 - PMODs (Bank7)
  09 - Configuration and ADC (Bank0)
  10 - FMC-LPC (Bank3/4/5)
  11 - Power CSI and Banks
  12 - Power Decoupling
  13 - Power Regulators
  14 - Power Block Diagram
- Notes:
  Resistors size 0402, tolerance 5%, unless otherwise specified.
  Ferrite Beads size 0402 unless otherwise specified.
  Capacitors >= 4.7uF size 0603 unless otherwise specified.
  Capacitors < 4.7uF size 0402 unless otherwise specified.
sheet 3
- Route USB pair 90 ohm impedance
- JP1 Reset FTDI
  Default Open
sheet 4
- OSCILLATOR
- LVDS RX Termination Resistors
- DNI
- NOTE: Place close to FPGA
- NOTE:
  1. Match length within pair <= 0.1mm, match length between pairs <=1.0mm.
  2. Differential impedance should be 100 ohms and 50 ohms as a single ended signal
  3. All the power rails should be capable of carrying 1A current
- Keep LEDs away from Camera
sheet 5
- Raspberry PI and User I/O Connector
- JP3 & JP4 Power For J5
  Default Open
- Bank6
- 3.3v (Default)
  1.8v Option
- DNI
- Layout:
  SS: Put box around Prototype Area
  SS: Row and Column Letters/Numbers
  Close to FMC-LPC and JP5
- Through Hole Prototype Area
sheet 6
- Serdes Bank
- PLL filter with DCR<=0.1 ohm
  DC must be <<5% drop across
  anti-resonance resistor under
  worst case
- Use little to no stub
  between selection
  resistors
- Place PLL series resistor,
  two  caps and r_ext right
  underneath the chip on the
  reverse side of the board
- R_ext is chosen for 100 ohm Diff
- DNI
- 1-2 = 125 Mhz (Default)
  2-3 = 200 Mhz
- DIP SWITCH
- Switch Signal Map
- Route SMA pairs as 100 ohm differential
- U3C Pin
- Signal
- SWITCH
- Bank2
- N14
- SWITCH0
- 1
- M14
- SWITCH1
- 2
- Minimize length as short as possible
  short_stub_trace. TP close to FPGA
- 3.3v
- M16
- SWITCH2
- 3
- M15
- SWITCH3
- 4
- N15
- SWITCH4
- 5
- N16
- SWITCH5
- 6
- Two 50 ohm Lookbacks Traces: 6 inches and 10 inches
  Place TPs close to FPGA
- M17
- SWITCH6
- 7
- M18
- SWITCH7
- 8
sheet 7
- LEDs Signal Map
- U3B pin
- Signal
- LED
- GSRN
- E17
- LED0
- D3
- F13
- LED1
- D4
- G13
- LED2
- D5
- F14
- LED3
- D6
- L16
- LED4
- D7
- L15
- LED5
- D8
- L20
- LED6
- D9
- L19
- LED7
- D10
- LEDs
- U3C pin
- Signal
- LED
- R17
- LED8
- D11
- R18
- LED9
- D12
- U20
- LED10
- D13
- T20
- LED11
- D14
- W20
- LED12
- D15
- V20
- LED13
- D16
- Bank1
- 3.3v
- Group LEDs 4,4,4,2
  12bit ADC shown groups of 4
  + 1 led for PWM brightness
  + 1 led for other use
sheet 8
- J17, J18 and J19 All Right-Angle PMOD connectors
- Bank7
- 3.3v
- PMOD2 unavailable when Bank0 / Flash set to 1.8V
